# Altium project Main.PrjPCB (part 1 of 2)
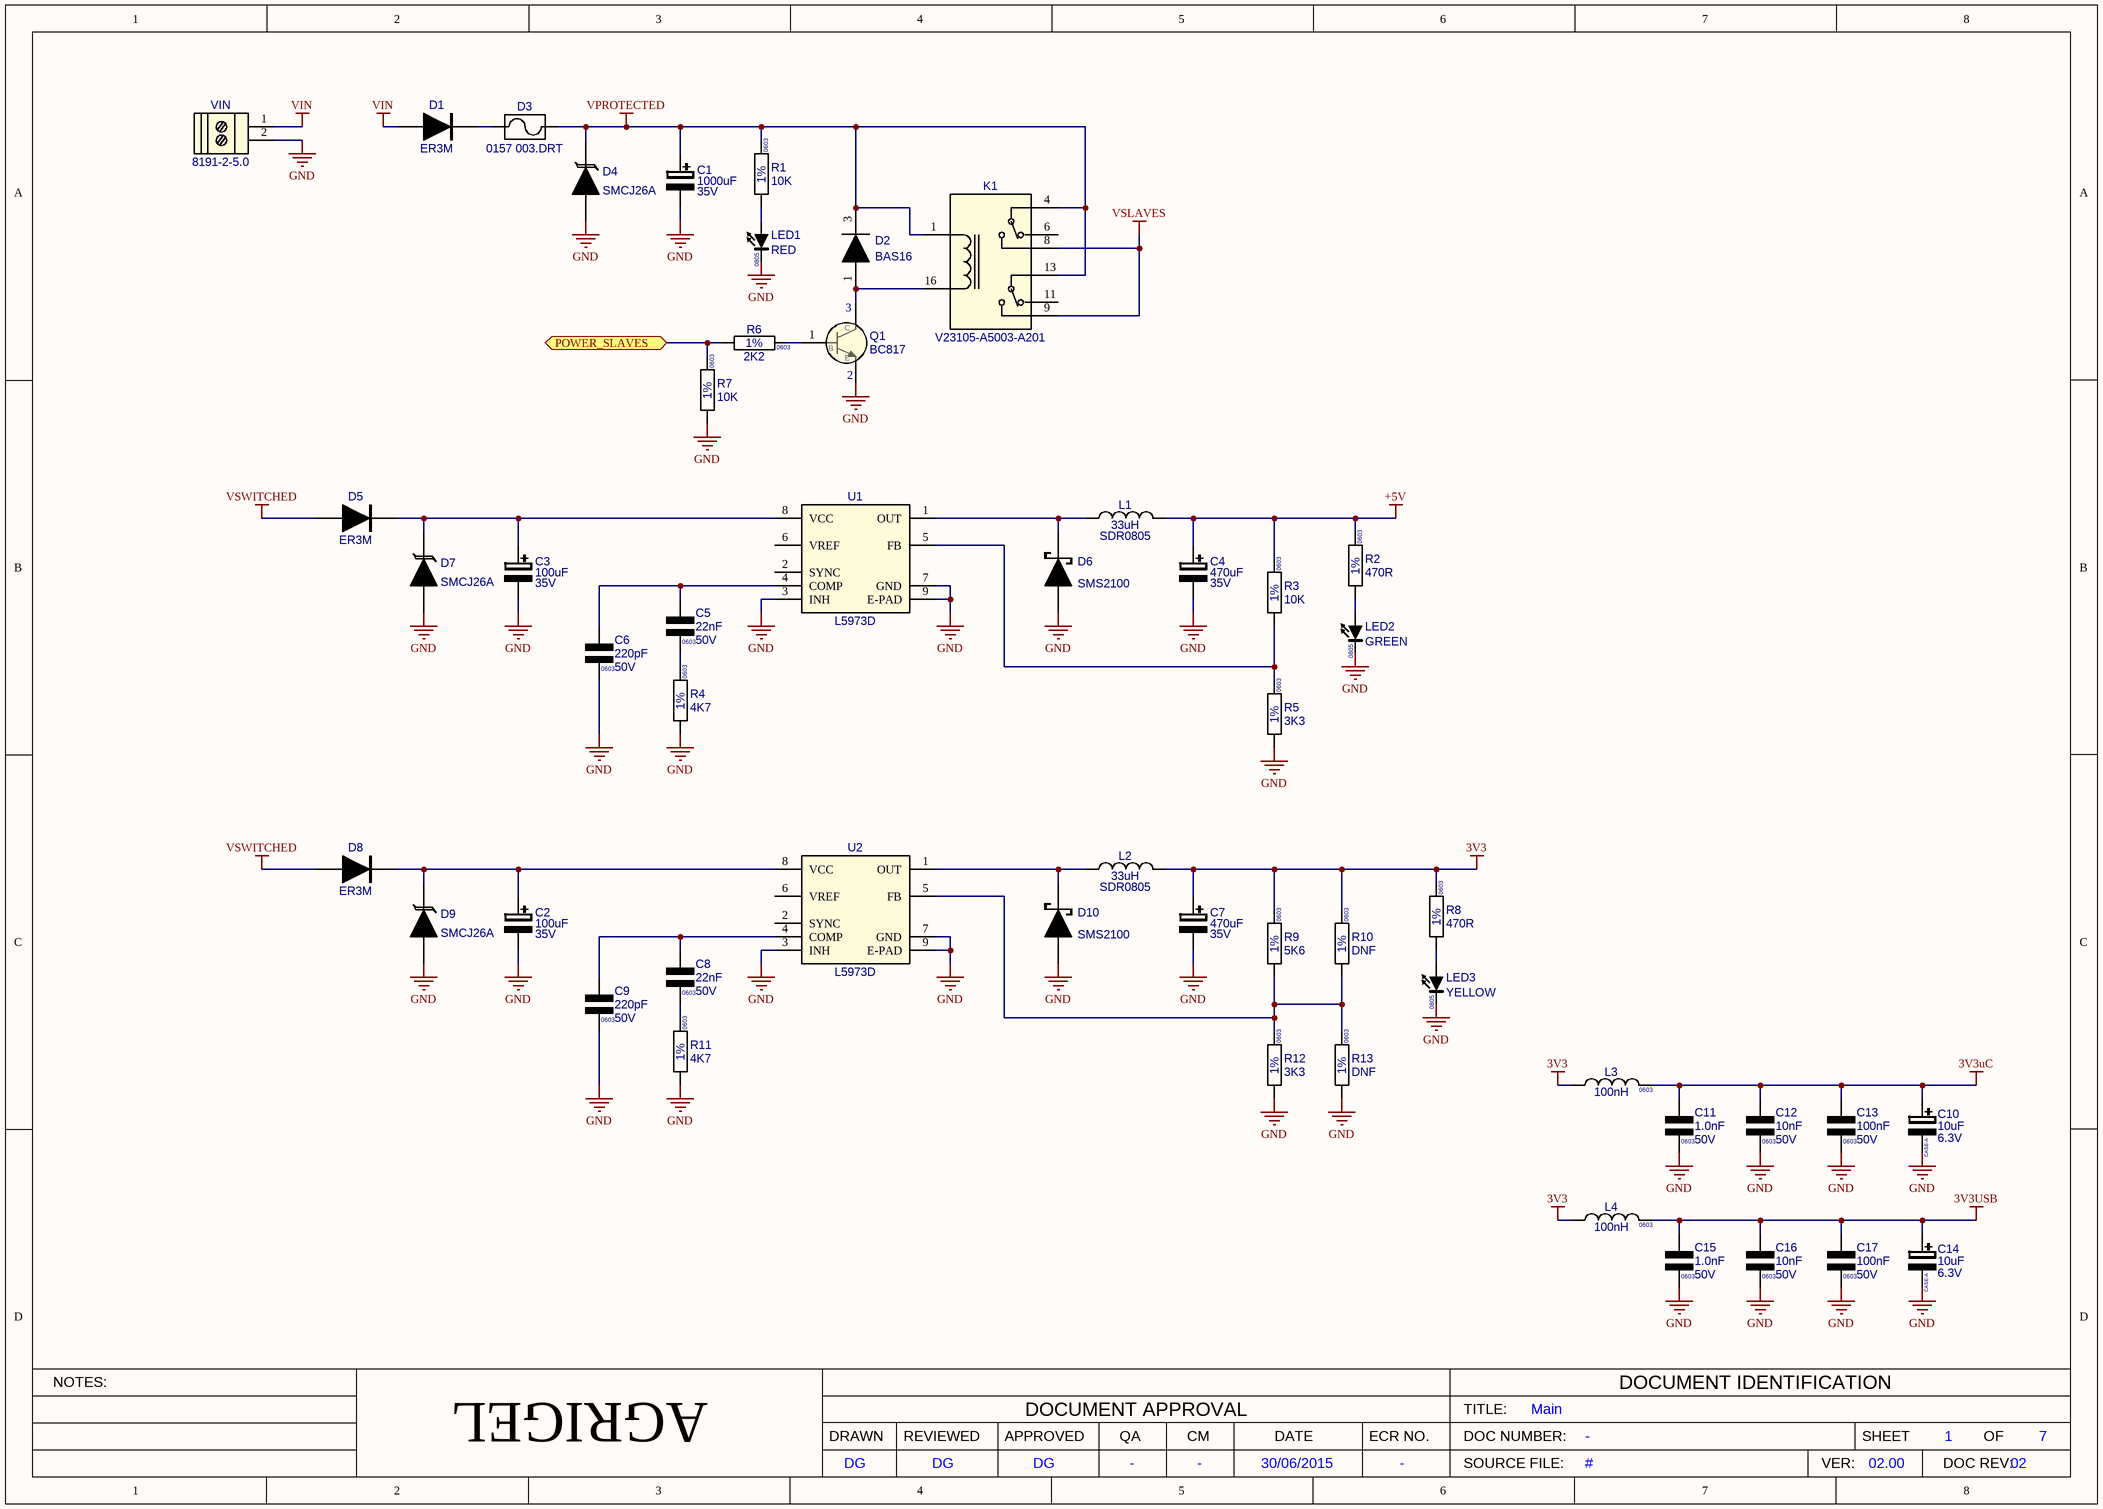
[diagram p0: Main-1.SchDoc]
Version_PCB Assy Instruction: 2; Version: 02.00; Spec_Solder Mask: GREEN; Spec_Silkscreen: WHITE EPOXY; Spec_PCB Thickness: 1.60mm; Spec_Cu Thickness: 35um; SCH_Title: Main; SCH_SheetTotal: 7; SCH_Reviewed: DG; SCH_QA: -; SCH_Number: -; SCH_FILENAME: Main-1.SCH; SCH_ECR: -; SCH_DRAWN: DG; SCH_DocRev: 02; SCH_Date: 30/06/2015; SCH_CM: -; SCH_Approved: DG; PRINT_DATE: 30/09/2014; PCB_TITLE: MAIN PCB; PCB_Plot File [Assy]: MAIN [Assy]; PCB_Plot File: MAIN [Panel]; PCB_ECRNo: -; PCB_Drawn: EDM; PCB_Drawing Number: -; PCB_DocRevision: 02; PCB_Company Name: AGRIGEL
7 sheets, 321 parts. Net scope: flat (ports and power ports of the same name join across sheets).
Board files: Main.PcbDoc, Main [Assy].PcbDoc, Main [Panel].PcbDoc
Sheets:
  Main-1.SchDoc
  Main-2.SchDoc
  Main-3.SchDoc
  Main-4.SchDoc
  Main-5.SchDoc
  Main-6.SchDoc
  Main-7.SchDoc

## Sheet Main-1.SchDoc: #
size A3; ApprovedBy: #; DrawnBy: #; DocumentNumber: 1; Revision: #; SheetNumber: 1; DocumentRevision: #; Reviewed: #; QA: #; CM: #; ECR: #; PageSetup: Record=PageOptions¦CenterHorizontal=True¦CenterVertical=True¦PrintScale=0.97¦XCorrection=1.00¦YCorrection=1.00¦PrintKind=1¦BorderSize=5000000¦LeftOffset=0¦BottomOffset=0¦Orientation=2¦PaperLength=1000¦PaperWidth=1000¦Scale=100¦PaperSource=7¦PrintQuality=-4¦MediaType=1¦DitherType=10¦PaperKind=A3¦PrintScaleMode=1

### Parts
C1  value 1000uF  Voltage: 35V  [EL-RAD-12.5x20]  (hidden comment: CAP-EL_1000uF_35V_20%-YXF)
C2  value 100uF  Voltage: 35V  [CAP-EL-SMD-10x10.5]  (hidden comment: 100uF35V-20%-EEVFC)
C3  value 100uF  Voltage: 35V  [CAP-EL-SMD-10x10.5]  (hidden comment: 100uF35V-20%-EEVFC)
C4  value 470uF  Voltage: 35V  [CAP-EL-SMD-10x10.5]  (hidden comment: 470uF-35V-20%-LZ)
C5  value 22nF  Voltage: 50V  Text1: 0603  [CAPC0603X85N]  (hidden comment: 22nF_C0603_50V_10%_X7R)
C6  value 220pF  Voltage: 50V  Text1: 0603  [CAPC0603X85N]  (hidden comment: 220pF_C0603_50V_10%_NP0)
C7  value 470uF  Voltage: 35V  [CAP-EL-SMD-10x10.5]  (hidden comment: 470uF-35V-20%-LZ)
C8  value 22nF  Voltage: 50V  Text1: 0603  [CAPC0603X85N]  (hidden comment: 22nF_C0603_50V_10%_X7R)
C9  value 220pF  Voltage: 50V  Text1: 0603  [CAPC0603X85N]  (hidden comment: 220pF_C0603_50V_10%_NP0)
C10  value 10uF  Voltage: 6.3V  Text1: CASE-A  [T491-A]  (hidden comment: 10uF_6.3V_T491A_20%)
C11  value 1.0nF  Voltage: 50V  Text1: 0603  [CAPC0603X85N]  (hidden comment: 1.0nF_C0603_50V_10%_X7R)
C12  value 10nF  Voltage: 50V  Text1: 0603  [CAPC0603X85N]  (hidden comment: 10nF_C0603_50V_10%_X7R)
C13  value 100nF  Voltage: 50V  Text1: 0603  [CAPC0603X85N]  (hidden comment: 100nF_C0603_50V_5%_X7R)
C14  value 10uF  Voltage: 6.3V  Text1: CASE-A  [T491-A]  (hidden comment: 10uF_6.3V_T491A_20%)
C15  value 1.0nF  Voltage: 50V  Text1: 0603  [CAPC0603X85N]  (hidden comment: 1.0nF_C0603_50V_10%_X7R)
C16  value 10nF  Voltage: 50V  Text1: 0603  [CAPC0603X85N]  (hidden comment: 10nF_C0603_50V_10%_X7R)
C17  value 100nF  Voltage: 50V  Text1: 0603  [CAPC0603X85N]  (hidden comment: 100nF_C0603_50V_5%_X7R)
D1  ER3M  [SMC]
D2  BAS16  [SOT23]
D3  Text1: 0157 003.DRT  [LF-0157]  (hidden comment: 0157003.DRT)
D4  SMCJ26A  [SMC]
D5  ER3M  [SMC]
D6  SMS2100  [DO-213AB]
D7  SMCJ26A  [SMC]
D8  ER3M  [SMC]
D9  SMCJ26A  [SMC]
D10  SMS2100  [DO-213AB]
K1  Part Number: V23105-A5003-A201  [REL-D2n]  (hidden comment: V23105-A5003-A201-12V)
L1  value 33uH  [SDR0805]  (hidden comment: SDR0805-330K)
L2  value 33uH  [SDR0805]  (hidden comment: SDR0805-330K)
L3  value 100nH  Text1: 0603  [L0603]  (hidden comment: 100nH-CI160808)
L4  value 100nH  Text1: 0603  [L0603]  (hidden comment: 100nH-CI160808)
LED1  value RED  Text2: 0805  [LED0805-Red]  (hidden comment: RED_0805_SMD)
LED2  value GREEN  Text2: 0805  [LED0805-Green]  (hidden comment: GREEN_0805_SMD)
LED3  value YELLOW  Text2: 0805  [LED0805-Yellow]  (hidden comment: YELLOW_0805_SMD)
Q1  BC817  [SOT23]
R1  value 10K  Tol: 1%  Text1: 0603  [RESC0603X60N]  (hidden comment: 10K_R0603_1%)
R2  value 470R  Tol: 1%  Text1: 0603  [RESC0603X60N]  (hidden comment: 470R_R0603_1%)
R3  value 10K  Tol: 1%  Text1: 0603  [RESC0603X60N]  (hidden comment: 10K_R0603_1%)
R4  value 4K7  Tol: 1%  Text1: 0603  [RESC0603X60N]  (hidden comment: 4K7_R0603_1%)
R5  value 3K3  Tol: 1%  Text1: 0603  [RESC0603X60N]  (hidden comment: 3K3_R0603_1%)
R6  value 2K2  Tol: 1%  Text1: 0603  [RESC0603X60N]  (hidden comment: 2K2_R0603_1%)
R7  value 10K  Tol: 1%  Text1: 0603  [RESC0603X60N]  (hidden comment: 10K_R0603_1%)
R8  value 470R  Tol: 1%  Text1: 0603  [RESC0603X60N]  (hidden comment: 470R_R0603_1%)
R9  value 5K6  Tol: 1%  Text1: 0603  [RESC0603X60N]  (hidden comment: 5K6_R0603_1%)
R10  value DNF  Tol: 1%  Text1: 0603  [RESC0603X60N]  (hidden comment: DNF_R0603_1%)
R11  value 4K7  Tol: 1%  Text1: 0603  [RESC0603X60N]  (hidden comment: 4K7_R0603_1%)
R12  value 3K3  Tol: 1%  Text1: 0603  [RESC0603X60N]  (hidden comment: 3K3_R0603_1%)
R13  value DNF  Tol: 1%  Text1: 0603  [RESC0603X60N]  (hidden comment: DNF_R0603_1%)
U1  Part Number: L5973D  [HSOP8]  (hidden comment: L5973D-HSOP8)
U2  Part Number: L5973D  [HSOP8]  (hidden comment: L5973D-HSOP8)
VIN  8191-2-5.0  [SCREW-TB-2-5.0]

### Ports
POWER_SLAVES

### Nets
3V3: C7.1 L2.2 L3.1 L4.1 R8.1 R9.1 R10.1
3V3uC: C10.1 C11.1 C12.1 C13.1 L3.2
3V3USB: C14.1 C15.1 C16.1 C17.1 L4.2
+5V: C4.1 L1.2 R2.1 R3.1
GND: C1.2 C2.2 C3.2 C4.2 C6.2 C7.2 C9.2 C10.2 C11.2 C12.2 C13.2 C14.2 C15.2 C16.2 C17.2 D4.2(A) D6.2(A) D7.2(A) D9.2(A) D10.2(A) LED1.1(K) LED2.1(K) LED3.1(K) Q1.2(E) R4.2 R5.2 R7.2 R11.2 R12.2 R13.2 U1.3(INH) U1.7(GND) U1.9(E-PAD) U2.3(INH) U2.7(GND) U2.9(E-PAD) VIN.2
VIN: D1.2(A) VIN.1
VPROTECTED: C1.1 D2.3(C) D3.2 D4.1(C) K1.1 K1.4 K1.13 R1.1
VSLAVES: K1.8 K1.9
VSWITCHED: D5.2(A) D8.2(A)
NetC2_1: C2.1 D8.1(C) D9.1(C) U2.8(VCC)
NetC3_1: C3.1 D5.1(C) D7.1(C) U1.8(VCC)
NetC5_1: C5.1 C6.1 U1.4(COMP)
NetC5_2: C5.2 R4.1
NetC8_1: C8.1 C9.1 U2.4(COMP)
NetC8_2: C8.2 R11.1
NetD1_1: D1.1(C) D3.1
NetD2_1: D2.1(A) K1.16 Q1.3(C)
NetD6_1: D6.1(C) L1.1 U1.1(OUT)
NetD10_1: D10.1(C) L2.1 U2.1(OUT)
NetLED1_2: LED1.2(A) R1.2
NetLED2_2: LED2.2(A) R2.2
NetLED3_2: LED3.2(A) R8.2
NetQ1_1: Q1.1(B) R6.2
NetR3_2: R3.2 R5.1 U1.5(FB)
NetR6_1: R6.1 R7.1 ; port POWER_SLAVES
NetR9_2: R9.2 R10.2 R12.1 R13.1 U2.5(FB)

Not connected (* = marked no-connect by the designer): K1 6 11; U1 2(SYNC) 6(VREF); U2 2(SYNC) 6(VREF)

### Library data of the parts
C1 = 1000uF_35V_20%_V-YXF: Cap Electrolytic THP Radial - Low Imp; Manufacturer: Rubycon; Part Number: 35YXF1000M; Tol: 20%; Reutech PN: 5910-EL-0063
C2 C3 = 100uF-35V-20%-EEVFC_V: Cap Electrolytic SMD Low Imp; Manufacturer: Panasonic; Part Number: EEVFC1V101P; Tol: 20%
C4 C7 = 470uF-35V-20%-LZ_V: Cap Electrolytic SMD Low Imp; Manufacturer: KJ Electronics; Part Number: 35LZ471MLC10×10.5EC; Tol: 20%
C5 C8 = 22nF_0603N_50V_10%_X7R_V: Cap Ceramic X7R; Manufacturer: Various; Part Number: 22nF 0603 50V 10% X7R; Board Tech: SMD; Tol: 10%
C6 C9 = 220pF_0603N_50V_10%_NP0_V: Cap Ceramic NP0; Manufacturer: Various; Part Number: 220pF 0603 50V 10% NP0; Board Tech: SMD; Tol: 10%
C10 C14 = 10uF_6.3V_CASE-A_20%_V: Cap Tantalum Case-A; Manufacturer: Various; Board Tech: SMD; Tol: 20%
C11 C15 = 1nF_0603N_50V_10%_X7R_V: Cap Ceramic X7R; Manufacturer: Various; Part Number: 1.0nF 0603 50V 10% X7R; Board Tech: SMD; Tol: 10%; Reutech PN: 5910-CA-0401
C12 C16 = 10nF_0603N_50V_10%_X7R_V: Cap Ceramic X7R; Manufacturer: Various; Part Number: 10nF 0603 50V 10% X7R; Board Tech: SMD; Tol: 10%; Reutech PN: 5910-CA-0402
C13 C17 = 100nF_0603N_50V_5%_X7R_V: Cap Ceramic X7R; Manufacturer: Various; Part Number: 100nF 0603 50V 5% X7R; Board Tech: SMD; Tol: 5%; Reutech PN: 5910-CA-0433
D1 D5 D8 = ER3M_SMC_H: Diode Rectifier (1000V 3A); Manufacturer: Diotec; Board Tech: SMD
D2 = BAS16_SOT23-3N_V: Diode Small Signal; Manufacturer: Fairchild; Board Tech: SMD
D3 = FUSE_0157003.DRT_3.0AMP: Fuse Clip and Nano Fuse; Manufacturer: Littelfuse; Board Tech: SMD; Value: 3.0A
D4 D7 D9 = SMCJ26A_V: TVS 1500W SMC; Manufacturer: Various; Board Tech: SMD
D6 D10 = SMS2100_V: Diode Schottky Rectifier 2Amp 100V; Manufacturer: Diotec; Board Tech: SMD; EDM-PN: DIO15
K1 = V23105-A5003-A201-12V: Relay DPDT 12V 3A; Manufacturer: Tyco/Axicom; Board Tech: THP
L1 L2 = 33uH_SDR0805_H: Inductor Power; Manufacturer: Bourns; Board Tech: SMD; Tol: 10%
L3 L4 = 100nH_CI160808_H: Inductor Chip SMD; Manufacturer: Bourns; Part Number: CI160808-R10J; Tol: 5%
LED1 = RED_0805_SMD_V: LED SMD 0805 Red; Manufacturer: Various; EDM-PN: LED7
LED2 = GREEN_0805_SMD_V: LED SMD 0805 Green; Manufacturer: Various; EDM-PN: LED17
LED3 = YELLOW_0805_SMD_V: LED SMD 0805 Yellow; Manufacturer: Various
Q1 = BC817_SOT23: Transistor NPN General Purpose; Manufacturer: Various; Board Tech: SMD; EDM-PN: TRN12
R1 R3 R7 = 10K_0603_V: Resistor Chip SMD; Manufacturer: Various; Part Number: 10K 0603 1%; Watt: 100mW; EDM-PN: RES120
R2 R8 = 470R_0603_V: Resistor Chip SMD; Manufacturer: Various; Part Number: 470R 0603 1%; Watt: 100mW; EDM-PN: RES127
R4 R11 = 4K7_0603_V: Resistor Chip SMD; Manufacturer: Various; Part Number: 4K7 0603 1%; Watt: 100mW
R5 R12 = 3K3_0603_V: Resistor Chip SMD; Manufacturer: Various; Part Number: 3K3 0603 1%; Watt: 100mW
R6 = 2K2_0603_H: Resistor Chip SMD; Manufacturer: Various; Part Number: 2K2 0603 1%; Watt: 100mW; EDM-PN: RES232
R9 = 5K6_0603_V: Resistor Chip SMD; Manufacturer: Various; Part Number: 5K6 0603 1%; Watt: 100mW
R10 R13 = DNF_0603_V: Resistor Chip SMD - Do not Fit; Manufacturer: Various; Watt: 100mW
U1 U2 = L5973D-HSOP8: IC Switching Regulator 2.5A; Manufacturer: ST; Board Tech: SMT
VIN = 8191-2-5.0: Screw Terminal 5.0mm Pitch; Manufacturer: Wieland; Board Tech: THP; Value: 25.161.0253.0

## Sheet Main-2.SchDoc: #
size A3; ApprovedBy: #; DrawnBy: #; DocumentNumber: 2; Revision: #; SheetNumber: 2; DocumentRevision: #; Reviewed: #; QA: #; CM: #; ECR: #; PageSetup: Record=PageOptions¦CenterHorizontal=True¦CenterVertical=True¦PrintScale=0.97¦XCorrection=1.00¦YCorrection=1.00¦PrintKind=1¦BorderSize=5000000¦LeftOffset=0¦BottomOffset=0¦Orientation=2¦PaperLength=1000¦PaperWidth=1000¦Scale=100¦PaperSource=7¦PrintQuality=-4¦MediaType=1¦DitherType=10¦PaperKind=A3¦PrintScaleMode=1
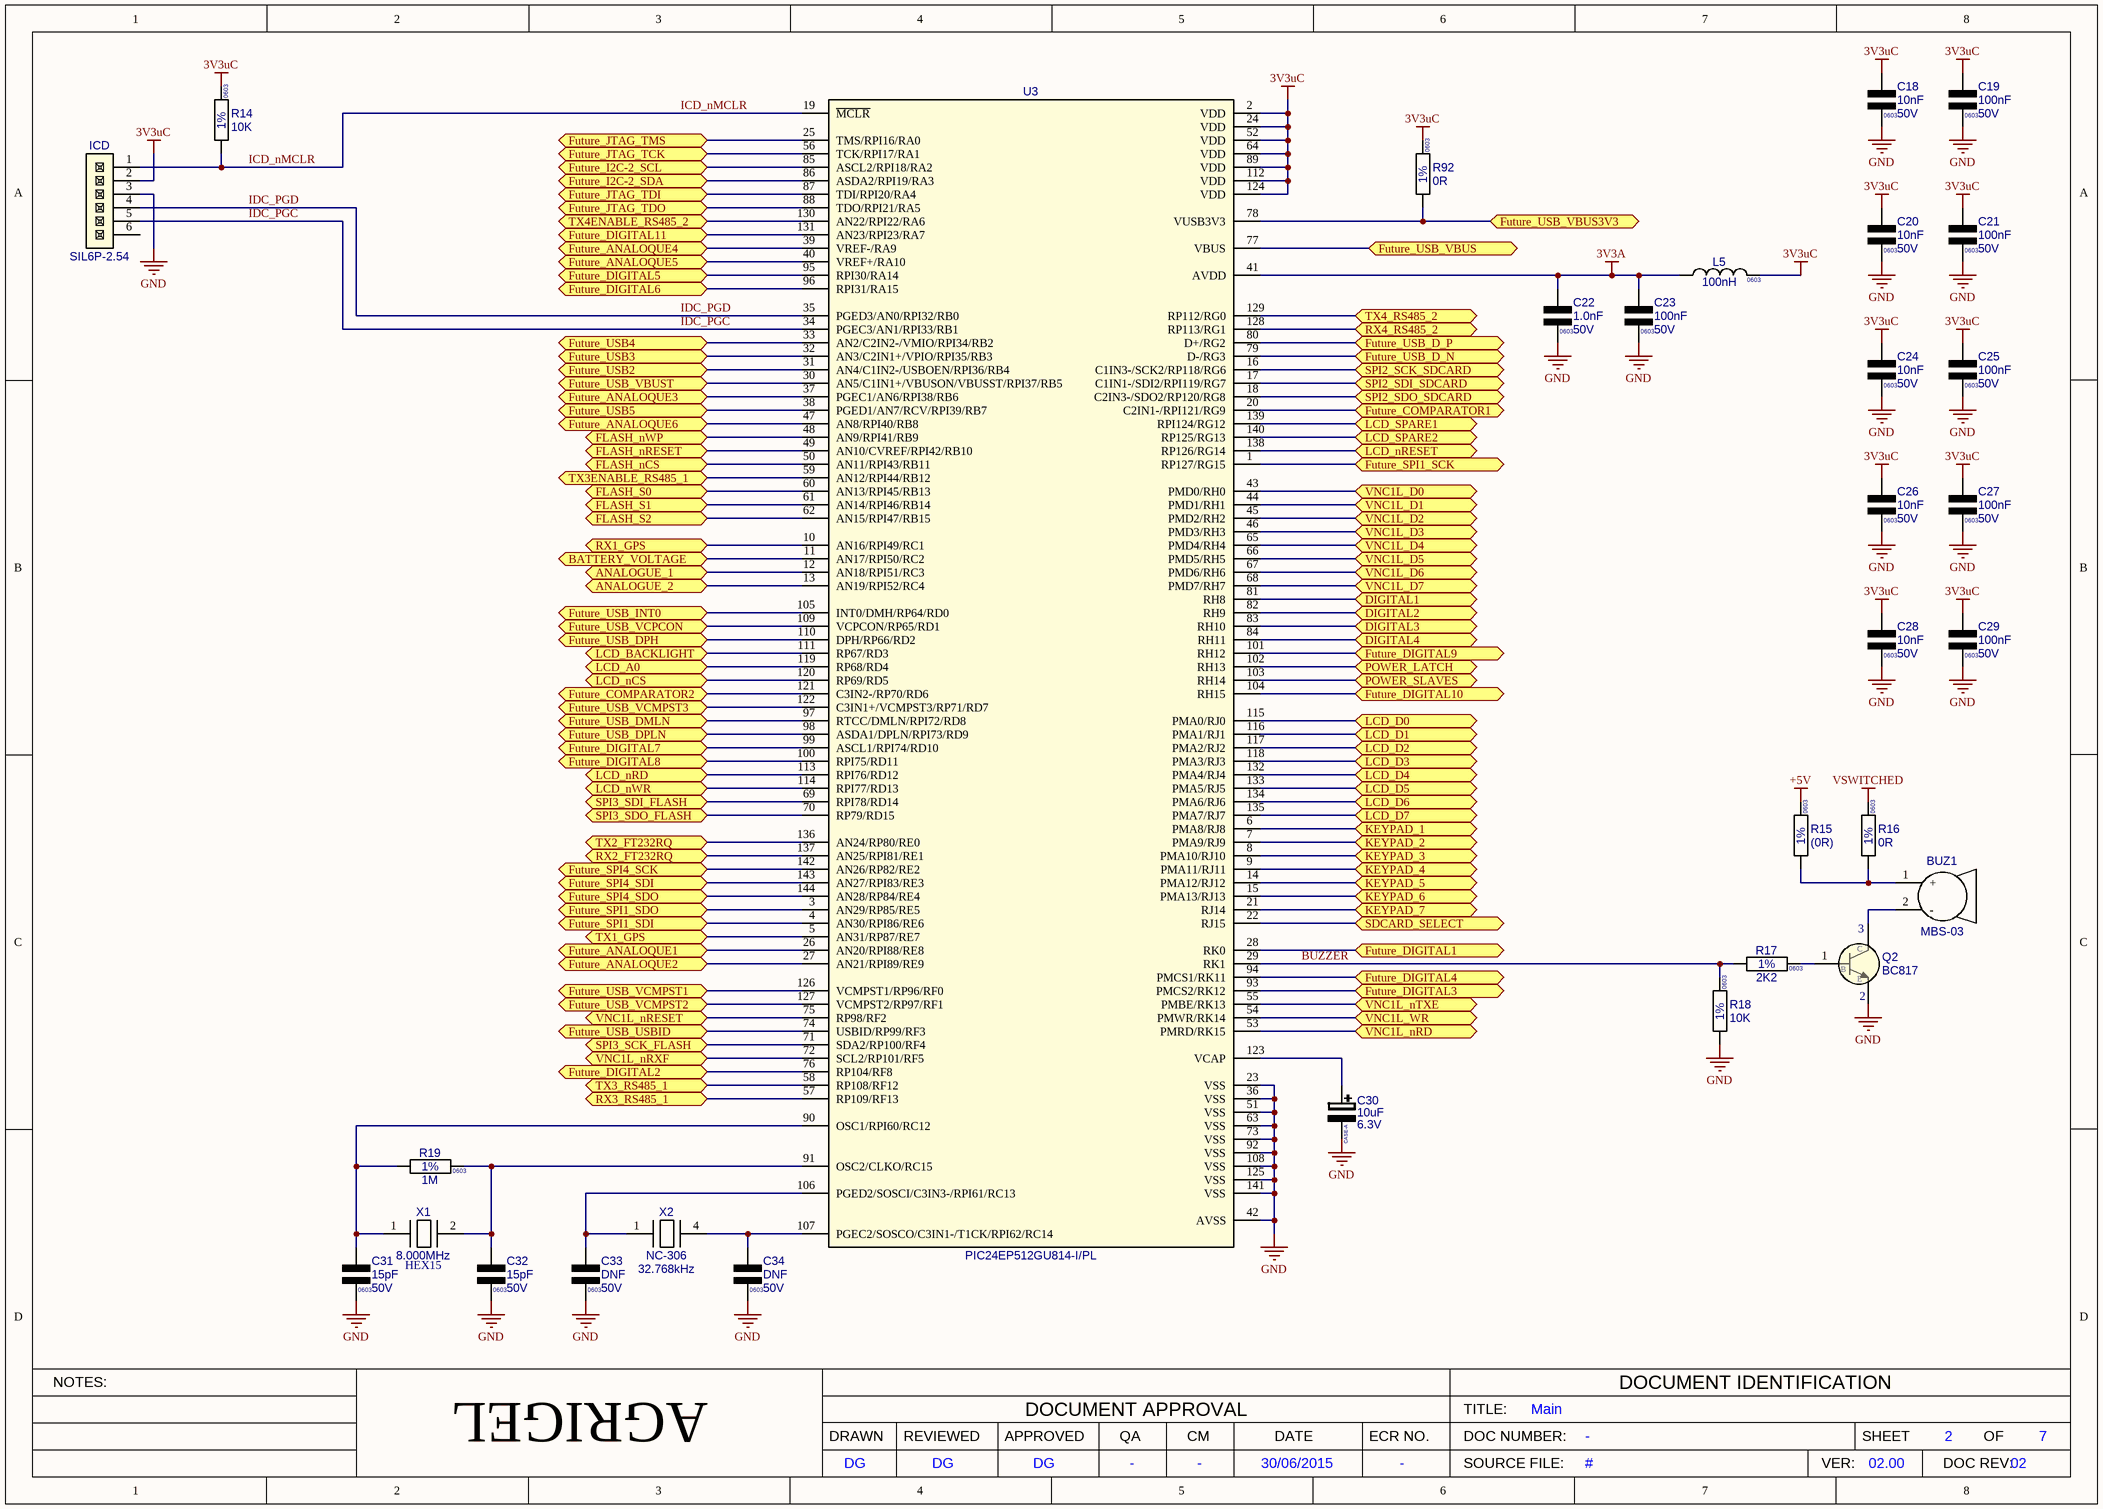
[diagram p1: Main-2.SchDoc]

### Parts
BUZ1  MBS-03  [Buzzer-MBS01-12]
C18  value 10nF  Voltage: 50V  Text1: 0603  [CAPC0603X85N]  (hidden comment: 10nF_C0603_50V_10%_X7R)
C19  value 100nF  Voltage: 50V  Text1: 0603  [CAPC0603X85N]  (hidden comment: 100nF_C0603_50V_5%_X7R)
C20  value 10nF  Voltage: 50V  Text1: 0603  [CAPC0603X85N]  (hidden comment: 10nF_C0603_50V_10%_X7R)
C21  value 100nF  Voltage: 50V  Text1: 0603  [CAPC0603X85N]  (hidden comment: 100nF_C0603_50V_5%_X7R)
C22  value 1.0nF  Voltage: 50V  Text1: 0603  [CAPC0603X85N]  (hidden comment: 1.0nF_C0603_50V_10%_X7R)
C23  value 100nF  Voltage: 50V  Text1: 0603  [CAPC0603X85N]  (hidden comment: 100nF_C0603_50V_5%_X7R)
C24  value 10nF  Voltage: 50V  Text1: 0603  [CAPC0603X85N]  (hidden comment: 10nF_C0603_50V_10%_X7R)
C25  value 100nF  Voltage: 50V  Text1: 0603  [CAPC0603X85N]  (hidden comment: 100nF_C0603_50V_5%_X7R)
C26  value 10nF  Voltage: 50V  Text1: 0603  [CAPC0603X85N]  (hidden comment: 10nF_C0603_50V_10%_X7R)
C27  value 100nF  Voltage: 50V  Text1: 0603  [CAPC0603X85N]  (hidden comment: 100nF_C0603_50V_5%_X7R)
C28  value 10nF  Voltage: 50V  Text1: 0603  [CAPC0603X85N]  (hidden comment: 10nF_C0603_50V_10%_X7R)
C29  value 100nF  Voltage: 50V  Text1: 0603  [CAPC0603X85N]  (hidden comment: 100nF_C0603_50V_5%_X7R)
C30  value 10uF  Voltage: 6.3V  Text1: CASE-A  [T491-A]  (hidden comment: 10uF_6.3V_T491A_20%)
C31  value 15pF  Voltage: 50V  Text1: 0603  [CAPC0603X85N]  (hidden comment: 15pF_C0603_50V_5%_NP0)
C32  value 15pF  Voltage: 50V  Text1: 0603  [CAPC0603X85N]  (hidden comment: 15pF_C0603_50V_5%_NP0)
C33  value DNF  Voltage: 50V  Text1: 0603  [CAPC0603X85N]  (hidden comment: DNF_C0603_50V_10%_X7R)
C34  value DNF  Voltage: 50V  Text1: 0603  [CAPC0603X85N]  (hidden comment: DNF_C0603_50V_10%_X7R)
ICD  SIL6P-2.54  [SIL6P-2.54]
L5  value 100nH  Text1: 0603  [L0603]  (hidden comment: 100nH-CI160808)
Q2  BC817  [SOT23]
R14  value 10K  Tol: 1%  Text1: 0603  [RESC0603X60N]  (hidden comment: 10K_R0603_1%)
R15  value (0R)  Tol: 1%  Text1: 0603  [RESC0603X60N]  (hidden comment: 0R_R0603_1%)
R16  value 0R  Tol: 1%  Text1: 0603  [RESC0603X60N]  (hidden comment: 0R_R0603_1%)
R17  value 2K2  Tol: 1%  Text1: 0603  [RESC0603X60N]  (hidden comment: 2K2_R0603_1%)
R18  value 10K  Tol: 1%  Text1: 0603  [RESC0603X60N]  (hidden comment: 10K_R0603_1%)
R19  value 1M  Tol: 1%  Text1: 0603  [RESC0603X60N]  (hidden comment: 1M_R0603_1%)
R92  value 0R  Tol: 1%  Text1: 0603  [RESC0603X60N]  (hidden comment: 0R_R0603_1%)
U3  PIC24EP512GU814-I/PL  [LQFP144-20x20]
X1  Text2: HEX15  Text1: 8.000MHz  [XT-HEX15]  (hidden comment: XTAL_8.000MHz_HEX15)
X2  Text1: NC-306  Part Number: 32.768kHz  [Xtal-SMD8.0x3.2 4Pin]  (hidden comment: 32.768kHz-NC-306)

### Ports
ANALOGUE_1, ANALOGUE_2, BATTERY_VOLTAGE, DIGITAL1, DIGITAL2, DIGITAL3, DIGITAL4, FLASH_nCS, FLASH_nRESET, FLASH_nWP, FLASH_S0, FLASH_S1, FLASH_S2, Future_ANALOQUE1, Future_ANALOQUE2, Future_ANALOQUE3, Future_ANALOQUE4, Future_ANALOQUE5, Future_ANALOQUE6, Future_COMPARATOR1, Future_COMPARATOR2, Future_DIGITAL1, Future_DIGITAL2, Future_DIGITAL3, Future_DIGITAL4, Future_DIGITAL5, Future_DIGITAL6, Future_DIGITAL7, Future_DIGITAL8, Future_DIGITAL9, Future_DIGITAL10, Future_DIGITAL11, Future_I2C-2_SCL, Future_I2C-2_SDA, Future_JTAG_TCK, Future_JTAG_TDI, Future_JTAG_TDO, Future_JTAG_TMS, Future_SPI1_SCK, Future_SPI1_SDI, Future_SPI1_SDO, Future_SPI4_SCK, Future_SPI4_SDI, Future_SPI4_SDO, Future_USB2, Future_USB3, Future_USB4, Future_USB5, Future_USB_D_N, Future_USB_D_P, Future_USB_DMLN, Future_USB_DPH, Future_USB_DPLN, Future_USB_INT0, Future_USB_USBID, Future_USB_VBUS, Future_USB_VBUS3V3, Future_USB_VBUST, Future_USB_VCMPST1, Future_USB_VCMPST2, Future_USB_VCMPST3, Future_USB_VCPCON, KEYPAD_1, KEYPAD_2, KEYPAD_3, KEYPAD_4, KEYPAD_5, KEYPAD_6, KEYPAD_7, LCD_A0, LCD_BACKLIGHT, LCD_D0, LCD_D1, LCD_D2, LCD_D3, LCD_D4, LCD_D5, LCD_D6, LCD_D7, LCD_nCS, LCD_nRD, LCD_nRESET, LCD_nWR, LCD_SPARE1, LCD_SPARE2, POWER_LATCH, POWER_SLAVES, RX1_GPS, RX2_FT232RQ, RX3_RS485_1, RX4_RS485_2, SDCARD_SELECT, SPI2_SCK_SDCARD, SPI2_SDI_SDCARD, SPI2_SDO_SDCARD, SPI3_SCK_FLASH, SPI3_SDI_FLASH, SPI3_SDO_FLASH, TX1_GPS, TX2_FT232RQ, TX3_RS485_1, TX3ENABLE_RS485_1, TX4_RS485_2, TX4ENABLE_RS485_2, VNC1L_D0, VNC1L_D1, VNC1L_D2, VNC1L_D3, VNC1L_D4, VNC1L_D5, VNC1L_D6, VNC1L_D7, VNC1L_nRD, VNC1L_nRESET, VNC1L_nRXF, VNC1L_nTXE, VNC1L_WR

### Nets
3V3A: C22.1 C23.1 L5.1 U3.41(AVDD)
3V3uC: C18.1 C19.1 C20.1 C21.1 C24.1 C25.1 C26.1 C27.1 C28.1 C29.1 ICD.2 L5.2 R14.1 R92.1 U3.2(VDD) U3.24(VDD) U3.52(VDD) U3.64(VDD) U3.89(VDD) U3.112(VDD) U3.124(VDD)
+5V: R15.1
GND: C18.2 C19.2 C20.2 C21.2 C22.2 C23.2 C24.2 C25.2 C26.2 C27.2 C28.2 C29.2 C30.2 C31.2 C32.2 C33.2 C34.2 ICD.3 Q2.2(E) R18.2 U3.23(VSS) U3.36(VSS) U3.42(AVSS) U3.51(VSS) U3.63(VSS) U3.73(VSS) U3.92(VSS) U3.108(VSS) U3.125(VSS) U3.141(VSS)
VSWITCHED: R16.1
BUZZER: R17.1 R18.1 U3.29(RK1)
ICD_nMCLR: ICD.1 R14.2 U3.19(~{MCLR})
IDC_PGC: ICD.5 U3.34(PGEC3/AN1/RPI33/RB1)
IDC_PGD: ICD.4 U3.35(PGED3/AN0/RPI32/RB0)
NetBUZ1_1: BUZ1.1(+) R15.2 R16.2
NetBUZ1_2: BUZ1.2(-) Q2.3(C)
NetC30_1: C30.1 U3.123(VCAP)
NetC31_1: C31.1 R19.1 U3.90(OSC1/RPI60/RC12) X1.1
NetC32_1: C32.1 R19.2 U3.91(OSC2/CLKO/RC15) X1.2
NetC33_1: C33.1 U3.106(PGED2/SOSCI/C3IN3-/RPI61/RC13) X2.1
NetC34_1: C34.1 U3.107(PGEC2/SOSCO/C3IN1-/T1CK/RPI62/RC14) X2.4
NetD16_2: U3.6(PMA8/RJ8) ; port KEYPAD_1
NetD18_2: U3.7(PMA9/RJ9) ; port KEYPAD_2
NetD21_2: U3.8(PMA10/RJ10) ; port KEYPAD_3
NetD23_2: U3.9(PMA11/RJ11) ; port KEYPAD_4
NetGPS1_20: U3.10(AN16/RPI49/RC1) ; port RX1_GPS
NetGPS1_21: U3.5(AN31/RP87/RE7) ; port TX1_GPS
NetLCD1_4: U3.119(RP68/RD4) ; port LCD_A0
NetLCD1_5: U3.114(RPI77/RD13) ; port LCD_nWR
NetLCD1_6: U3.113(RPI76/RD12) ; port LCD_nRD
NetLCD1_7: U3.115(PMA0/RJ0) ; port LCD_D0
NetLCD1_8: U3.116(PMA1/RJ1) ; port LCD_D1
NetLCD1_9: U3.117(PMA2/RJ2) ; port LCD_D2
NetLCD1_10: U3.118(PMA3/RJ3) ; port LCD_D3
NetLCD1_11: U3.132(PMA4/RJ4) ; port LCD_D4
NetLCD1_12: U3.133(PMA5/RJ5) ; port LCD_D5
NetLCD1_13: U3.134(PMA6/RJ6) ; port LCD_D6
NetLCD1_14: U3.135(PMA7/RJ7) ; port LCD_D7
NetLCD1_15: U3.120(RP69/RD5) ; port LCD_nCS
NetLCD1_16: U3.138(RP126/RG14) ; port LCD_nRESET
NetLCD-SPR1_1: U3.139(RPI124/RG12) ; port LCD_SPARE1
NetLCD-SPR2_1: U3.140(RP125/RG13) ; port LCD_SPARE2
NetP3_9: U3.1(RP127/RG15) ; port Future_SPI1_SCK
NetP3_10: U3.3(AN29/RP85/RE5) ; port Future_SPI1_SDO
NetP3_11: U3.4(AN30/RPI86/RE6) ; port Future_SPI1_SDI
NetP3_14: U3.20(C2IN1-/RPI121/RG9) ; port Future_COMPARATOR1
NetP3_15: U3.25(TMS/RPI16/RA0) ; port Future_JTAG_TMS
NetP3_16: U3.26(AN20/RPI88/RE8) ; port Future_ANALOQUE1
NetP3_17: U3.27(AN21/RPI89/RE9) ; port Future_ANALOQUE2
NetP3_18: U3.28(RK0) ; port Future_DIGITAL1
NetP3_19: U3.30(AN5/C1IN1+/VBUSON/VBUSST/RPI37/RB5) ; port Future_USB_VBUST
NetP3_20: U3.31(AN4/C1IN2-/USBOEN/RPI36/RB4) ; port Future_USB2
NetP3_21: U3.32(AN3/C2IN1+/VPIO/RPI35/RB3) ; port Future_USB3
NetP3_22: U3.33(AN2/C2IN2-/VMIO/RPI34/RB2) ; port Future_USB4
NetP3_23: U3.37(PGEC1/AN6/RPI38/RB6) ; port Future_ANALOQUE3
NetP3_24: U3.38(PGED1/AN7/RCV/RPI39/RB7) ; port Future_USB5
NetP3_25: U3.39(VREF-/RA9) ; port Future_ANALOQUE4
NetP3_26: U3.40(VREF+/RA10) ; port Future_ANALOQUE5
NetP3_27: U3.47(AN8/RPI40/RB8) ; port Future_ANALOQUE6
NetP3_28: U3.56(TCK/RPI17/RA1) ; port Future_JTAG_TCK
NetP3_29: U3.74(USBID/RP99/RF3) ; port Future_USB_USBID
NetP3_30: U3.76(RP104/RF8) ; port Future_DIGITAL2
NetP3_31: U3.77(VBUS) ; port Future_USB_VBUS
NetP3_32: R92.2 U3.78(VUSB3V3) ; port Future_USB_VBUS3V3
NetP3_33: U3.79(D-/RG3) ; port Future_USB_D_N
NetP3_34: U3.80(D+/RG2) ; port Future_USB_D_P
NetP4_9: U3.85(ASCL2/RPI18/RA2) ; port Future_I2C-2_SCL
NetP4_10: U3.86(ASDA2/RPI19/RA3) ; port Future_I2C-2_SDA
NetP4_11: U3.87(TDI/RPI20/RA4) ; port Future_JTAG_TDI
NetP4_12: U3.88(TDO/RPI21/RA5) ; port Future_JTAG_TDO
NetP4_13: U3.93(PMCS2/RK12) ; port Future_DIGITAL3
NetP4_14: U3.94(PMCS1/RK11) ; port Future_DIGITAL4
NetP4_15: U3.95(RPI30/RA14) ; port Future_DIGITAL5
NetP4_16: U3.96(RPI31/RA15) ; port Future_DIGITAL6
NetP4_17: U3.97(RTCC/DMLN/RPI72/RD8) ; port Future_USB_DMLN
NetP4_18: U3.98(ASDA1/DPLN/RPI73/RD9) ; port Future_USB_DPLN
NetP4_19: U3.99(ASCL1/RPI74/RD10) ; port Future_DIGITAL7
NetP4_20: U3.100(RPI75/RD11) ; port Future_DIGITAL8
NetP4_21: U3.101(RH12) ; port Future_DIGITAL9
NetP4_22: U3.104(RH15) ; port Future_DIGITAL10
NetP4_23: U3.105(INT0/DMH/RP64/RD0) ; port Future_USB_INT0
NetP4_24: U3.109(VCPCON/RP65/RD1) ; port Future_USB_VCPCON
NetP4_25: U3.110(DPH/RP66/RD2) ; port Future_USB_DPH
NetP4_26: U3.121(C3IN2-/RP70/RD6) ; port Future_COMPARATOR2
NetP4_27: U3.122(C3IN1+/VCMPST3/RP71/RD7) ; port Future_USB_VCMPST3
NetP4_28: U3.126(VCMPST1/RP96/RF0) ; port Future_USB_VCMPST1
NetP4_29: U3.127(VCMPST2/RP97/RF1) ; port Future_USB_VCMPST2
NetP4_30: U3.131(AN23/RPI23/RA7) ; port Future_DIGITAL11
NetP4_31: U3.142(AN26/RP82/RE2) ; port Future_SPI4_SCK
NetP4_32: U3.143(AN27/RPI83/RE3) ; port Future_SPI4_SDI
NetP4_33: U3.144(AN28/RP84/RE4) ; port Future_SPI4_SDO
NetQ2_1: Q2.1(B) R17.2
NetQ4_3: U3.81(RH8) ; port DIGITAL1
NetQ6_3: U3.82(RH9) ; port DIGITAL2
NetQ9_3: U3.83(RH10) ; port DIGITAL3
NetQ12_3: U3.84(RH11) ; port DIGITAL4
NetQ17_3: U3.14(PMA12/RJ12) ; port KEYPAD_5
NetQ18_3: U3.15(PMA13/RJ13) ; port KEYPAD_6
NetQ20_3: U3.21(RJ14) ; port KEYPAD_7
NetR6_1: U3.103(RH14) ; port POWER_SLAVES
NetR23_2: U3.11(AN17/RPI50/RC2) ; port BATTERY_VOLTAGE
NetR31_2: U3.12(AN18/RPI51/RC3) ; port ANALOGUE_1
NetR39_2: U3.13(AN19/RPI52/RC4) ; port ANALOGUE_2
NetR47_2: U3.58(RP108/RF12) ; port TX3_RS485_1
NetR53_1: U3.59(AN12/RPI44/RB12) ; port TX3ENABLE_RS485_1
NetR60_2: U3.129(RP112/RG0) ; port TX4_RS485_2
NetR67_1: U3.130(AN22/RPI22/RA6) ; port TX4ENABLE_RS485_2
NetR73_1: U3.48(AN9/RPI41/RB9) ; port FLASH_nWP
NetR74_2: U3.50(AN11/RPI43/RB11) ; port FLASH_nCS
NetR93_1: U3.111(RP67/RD3) ; port LCD_BACKLIGHT
NetR103_1: U3.102(RH13) ; port POWER_LATCH
NetR106_1: U3.75(RP98/RF2) ; port VNC1L_nRESET
NetR130_2: U3.43(PMD0/RH0) ; port VNC1L_D0
NetR131_2: U3.44(PMD1/RH1) ; port VNC1L_D1
NetR132_2: U3.45(PMD2/RH2) ; port VNC1L_D2
NetR133_2: U3.46(PMD3/RH3) ; port VNC1L_D3
NetSD1_2: U3.22(RJ15) ; port SDCARD_SELECT
NetSD1_3: U3.18(C2IN3-/SDO2/RP120/RG8) ; port SPI2_SDO_SDCARD
NetSD1_5: U3.16(C1IN3-/SCK2/RP118/RG6) ; port SPI2_SCK_SDCARD
NetSD1_7: U3.17(C1IN1-/SDI2/RPI119/RG7) ; port SPI2_SDI_SDCARD
NetU3_49: U3.49(AN10/CVREF/RPI42/RB10) ; port FLASH_nRESET
NetU3_53: U3.53(PMRD/RK15) ; port VNC1L_nRD
NetU3_54: U3.54(PMWR/RK14) ; port VNC1L_WR
NetU3_55: U3.55(PMBE/RK13) ; port VNC1L_nTXE
NetU3_57: U3.57(RP109/RF13) ; port RX3_RS485_1
NetU3_60: U3.60(AN13/RPI45/RB13) ; port FLASH_S0
NetU3_61: U3.61(AN14/RPI46/RB14) ; port FLASH_S1
NetU3_62: U3.62(AN15/RPI47/RB15) ; port FLASH_S2
NetU3_65: U3.65(PMD4/RH4) ; port VNC1L_D4
NetU3_66: U3.66(PMD5/RH5) ; port VNC1L_D5
NetU3_67: U3.67(PMD6/RH6) ; port VNC1L_D6
NetU3_68: U3.68(PMD7/RH7) ; port VNC1L_D7
NetU3_69: U3.69(RPI78/RD14) ; port SPI3_SDI_FLASH
NetU3_70: U3.70(RP79/RD15) ; port SPI3_SDO_FLASH
NetU3_71: U3.71(SDA2/RP100/RF4) ; port SPI3_SCK_FLASH
NetU3_72: U3.72(SCL2/RP101/RF5) ; port VNC1L_nRXF
NetU3_128: U3.128(RP113/RG1) ; port RX4_RS485_2
NetU3_136: U3.136(AN24/RP80/RE0) ; port TX2_FT232RQ
NetU3_137: U3.137(AN25/RPI81/RE1) ; port RX2_FT232RQ

Not connected (* = marked no-connect by the designer): ICD 6

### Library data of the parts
BUZ1 = BUZZER_MBS-03_THP: Buzzer Magnetic; Manufacturer: KAYER INDUSTRIAL; Board Tech: THP
C18 C20 C24 C26 C28 = 10nF_0603N_50V_10%_X7R_V: as C12 on sheet Main-1
C19 C21 C23 C25 C27 C29 = 100nF_0603N_50V_5%_X7R_V: as C13 on sheet Main-1
C22 = 1nF_0603N_50V_10%_X7R_V: as C11 on sheet Main-1
C30 = 10uF_6.3V_CASE-A_20%_V: as C10 on sheet Main-1
C31 C32 = 15pF_0603N_50V_5%_NP0_V: Cap Ceramic NP0; Manufacturer: Various; Part Number: 15pF 0603 50V 5% NP0; Board Tech: SMD; Tol: 5%
C33 C34 = DNF_0603N_50V_10%_X7R_V: Cap Ceramic X7R - Do not Fit; Manufacturer: Various; Board Tech: SMD; Tol: 10%
ICD = SIL6P-2.54: Header SIL Male THP, 2.54mm Pitch; Manufacturer: Various
L5 = 100nH_CI160808_H: as L3 on sheet Main-1
Q2 = BC817_SOT23: as Q1 on sheet Main-1
R14 R18 = 10K_0603_V: as R1 on sheet Main-1
R15 = 0R_0603_V-DNF: Resistor Chip SMD - Do not Fit; Manufacturer: Various; Part Number: DNF - 0R 0603 1%; Watt: 100mW
R16 R92 = 0R_0603_V: Resistor Chip SMD; Manufacturer: Various; Part Number: 0R 0603 1%; Watt: 100mW; EDM-PN: RES117
R17 = 2K2_0603_H: as R6 on sheet Main-1
R19 = 1M_0603_H: Resistor Chip SMD; Manufacturer: Various; Part Number: 1M 0603 1%; Watt: 100mW
U3 = PIC24EP512GU814-I/PL_LQFP144: IC Microcontroller 16-Bit and Digital Signal Controller; Manufacturer: Microchip; Board Tech: SMD
X1 = XTAL_8.000MHz_HEX15: Crystal - HEX15; Manufacturer: Horizon; Part Number: 8.000MHz HEX15; Board Tech: SMD; Value: XTAL_8.000MHz-HEX15
X2 = XTAL_32.768kHz-NC-306: Crystal - NC-306 (12pF); Manufacturer: Arrow; Board Tech: SMD; EDM-PN: CRY41; Value: NC-306 32.768kHz

## Sheet Main-3.SchDoc: #
size A3; ApprovedBy: #; DrawnBy: #; DocumentNumber: 3; Revision: #; SheetNumber: 3; DocumentRevision: #; Reviewed: #; QA: #; CM: #; ECR: #; PageSetup: Record=PageOptions|CenterHorizontal=True|CenterVertical=True|PrintScale=0.97|XCorrection=1.00|YCorrection=1.00|PrintKind=1|BorderSize=5000000|LeftOffset=0|BottomOffset=0|Orientation=2|PaperLength=1000|PaperWidth=1000|Scale=100|PaperSource=7|PrintQuality=-4|MediaType=1|DitherType=10|PaperKind=A3|PrintScaleMode=1
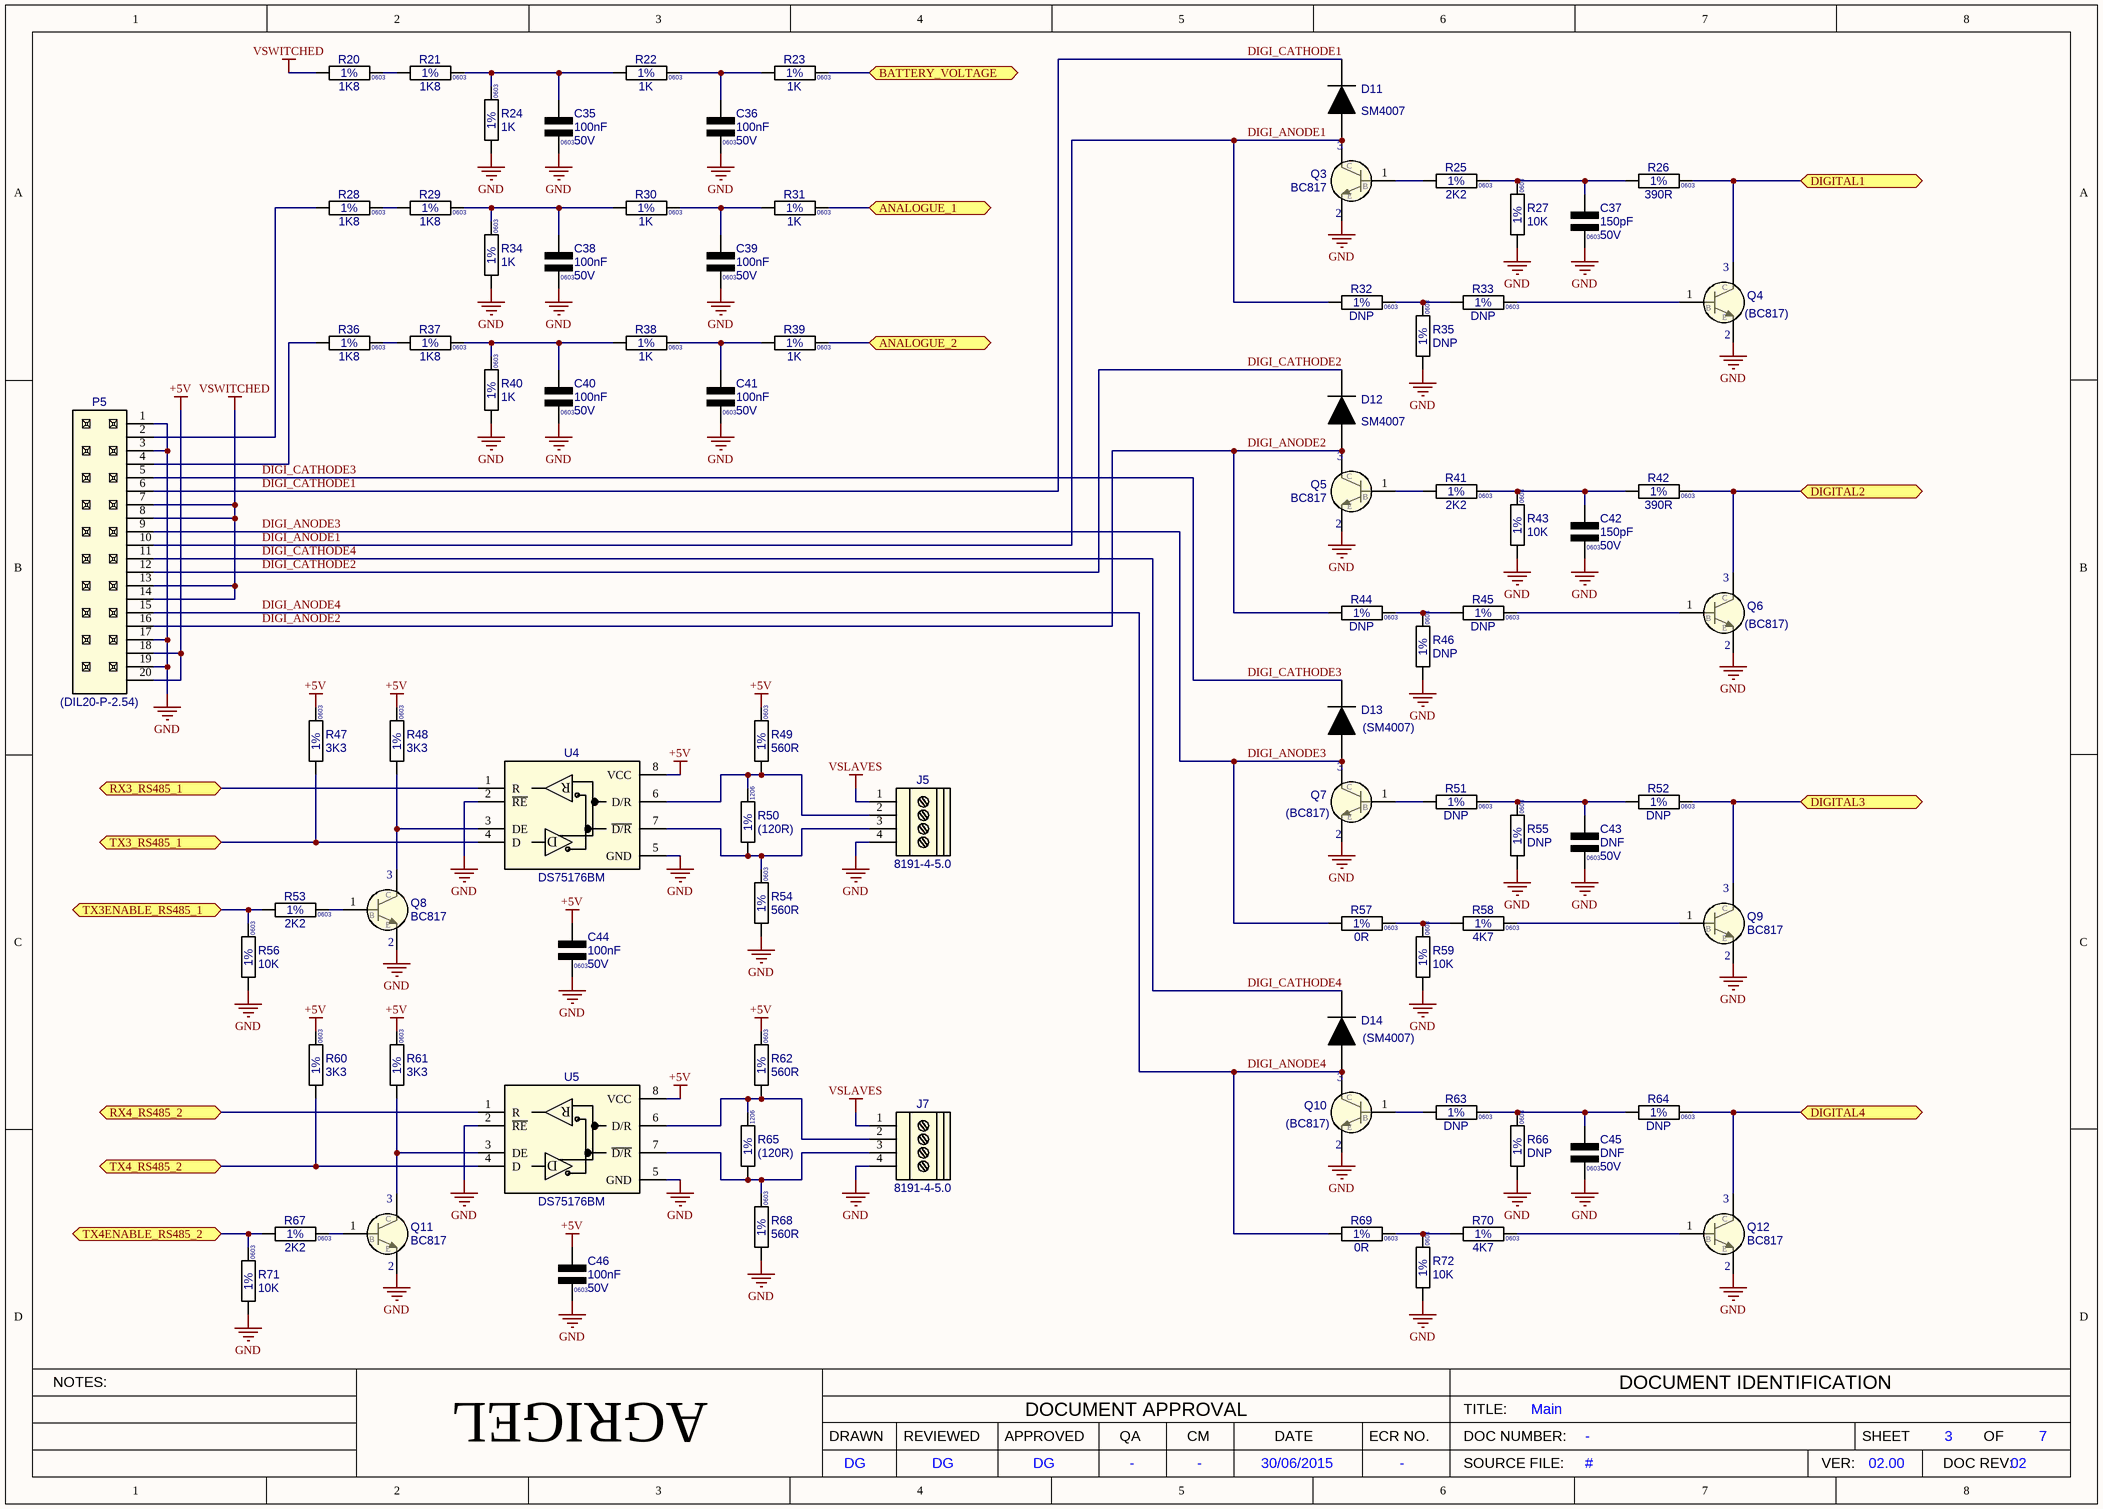
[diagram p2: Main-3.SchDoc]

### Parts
C35  value 100nF  Voltage: 50V  Text1: 0603  [CAPC0603X85N]  (hidden comment: 100nF_C0603_50V_5%_X7R)
C36  value 100nF  Voltage: 50V  Text1: 0603  [CAPC0603X85N]  (hidden comment: 100nF_C0603_50V_5%_X7R)
C37  value 150pF  Voltage: 50V  Text1: 0603  [CAPC0603X85N]  (hidden comment: 150pF_C0603_50V_5%_NP0)
C38  value 100nF  Voltage: 50V  Text1: 0603  [CAPC0603X85N]  (hidden comment: 100nF_C0603_50V_5%_X7R)
C39  value 100nF  Voltage: 50V  Text1: 0603  [CAPC0603X85N]  (hidden comment: 100nF_C0603_50V_5%_X7R)
C40  value 100nF  Voltage: 50V  Text1: 0603  [CAPC0603X85N]  (hidden comment: 100nF_C0603_50V_5%_X7R)
C41  value 100nF  Voltage: 50V  Text1: 0603  [CAPC0603X85N]  (hidden comment: 100nF_C0603_50V_5%_X7R)
C42  value 150pF  Voltage: 50V  Text1: 0603  [CAPC0603X85N]  (hidden comment: 150pF_C0603_50V_5%_NP0)
C43  value DNF  Voltage: 50V  Text1: 0603  [CAPC0603X85N]  (hidden comment: DNF_C0603_50V_10%_X7R)
C44  value 100nF  Voltage: 50V  Text1: 0603  [CAPC0603X85N]  (hidden comment: 100nF_C0603_50V_5%_X7R)
C45  value DNF  Voltage: 50V  Text1: 0603  [CAPC0603X85N]  (hidden comment: DNF_C0603_50V_10%_X7R)
C46  value 100nF  Voltage: 50V  Text1: 0603  [CAPC0603X85N]  (hidden comment: 100nF_C0603_50V_5%_X7R)
D11  SM4007  [DO-213AB]
D12  SM4007  [DO-213AB]
D13  value (SM4007)  [DO-213AB]  (hidden comment: SM4007-DNF)
D14  value (SM4007)  [DO-213AB]  (hidden comment: SM4007-DNF)
J5  8191-4-5.0  [SCREW-TB-4-5.0]
J7  8191-4-5.0  [SCREW-TB-4-5.0]
P5  value (DIL20-P-2.54)  [DIL20-P-2.54]  (hidden comment: DIL20P-2.54-DNF)
Q3  BC817  [SOT23]
Q4  value (BC817)  [SOT23]  (hidden comment: BC817-DNF)
Q5  BC817  [SOT23]
Q6  value (BC817)  [SOT23]  (hidden comment: BC817-DNF)
Q7  value (BC817)  [SOT23]  (hidden comment: BC817-DNF)
Q8  BC817  [SOT23]
Q9  BC817  [SOT23]
Q10  value (BC817)  [SOT23]  (hidden comment: BC817-DNF)
Q11  BC817  [SOT23]
Q12  BC817  [SOT23]
R20  value 1K8  Tol: 1%  Text1: 0603  [RESC0603X60N]  (hidden comment: 1K8_R0603_1%)
R21  value 1K8  Tol: 1%  Text1: 0603  [RESC0603X60N]  (hidden comment: 1K8_R0603_1%)
R22  value 1K  Tol: 1%  Text1: 0603  [RESC0603X60N]  (hidden comment: 1K_R0603_1%)
R23  value 1K  Tol: 1%  Text1: 0603  [RESC0603X60N]  (hidden comment: 1K_R0603_1%)
R24  value 1K  Tol: 1%  Text1: 0603  [RESC0603X60N]  (hidden comment: 1K_R0603_1%)
R25  value 2K2  Tol: 1%  Text1: 0603  [RESC0603X60N]  (hidden comment: 2K2_R0603_1%)
R26  value 390R  Tol: 1%  Text1: 0603  [RESC0603X60N]  (hidden comment: 390R_R0603_1%)
R27  value 10K  Tol: 1%  Text1: 0603  [RESC0603X60N]  (hidden comment: 10K_R0603_1%)
R28  value 1K8  Tol: 1%  Text1: 0603  [RESC0603X60N]  (hidden comment: 1K8_R0603_1%)
R29  value 1K8  Tol: 1%  Text1: 0603  [RESC0603X60N]  (hidden comment: 1K8_R0603_1%)
R30  value 1K  Tol: 1%  Text1: 0603  [RESC0603X60N]  (hidden comment: 1K_R0603_1%)
R31  value 1K  Tol: 1%  Text1: 0603  [RESC0603X60N]  (hidden comment: 1K_R0603_1%)
R32  value DNP  Tol: 1%  Text1: 0603  [RESC0603X60N]  (hidden comment: DNP_R0603_1%)
R33  value DNP  Tol: 1%  Text1: 0603  [RESC0603X60N]  (hidden comment: DNP_R0603_1%)
R34  value 1K  Tol: 1%  Text1: 0603  [RESC0603X60N]  (hidden comment: 1K_R0603_1%)
R35  value DNP  Tol: 1%  Text1: 0603  [RESC0603X60N]  (hidden comment: DNP_R0603_1%)
R36  value 1K8  Tol: 1%  Text1: 0603  [RESC0603X60N]  (hidden comment: 1K8_R0603_1%)
R37  value 1K8  Tol: 1%  Text1: 0603  [RESC0603X60N]  (hidden comment: 1K8_R0603_1%)
R38  value 1K  Tol: 1%  Text1: 0603  [RESC0603X60N]  (hidden comment: 1K_R0603_1%)
R39  value 1K  Tol: 1%  Text1: 0603  [RESC0603X60N]  (hidden comment: 1K_R0603_1%)
R40  value 1K  Tol: 1%  Text1: 0603  [RESC0603X60N]  (hidden comment: 1K_R0603_1%)
R41  value 2K2  Tol: 1%  Text1: 0603  [RESC0603X60N]  (hidden comment: 2K2_R0603_1%)
R42  value 390R  Tol: 1%  Text1: 0603  [RESC0603X60N]  (hidden comment: 390R_R0603_1%)
R43  value 10K  Tol: 1%  Text1: 0603  [RESC0603X60N]  (hidden comment: 10K_R0603_1%)
R44  value DNP  Tol: 1%  Text1: 0603  [RESC0603X60N]  (hidden comment: DNP_R0603_1%)
R45  value DNP  Tol: 1%  Text1: 0603  [RESC0603X60N]  (hidden comment: DNP_R0603_1%)
R46  value DNP  Tol: 1%  Text1: 0603  [RESC0603X60N]  (hidden comment: DNP_R0603_1%)
R47  value 3K3  Tol: 1%  Text1: 0603  [RESC0603X60N]  (hidden comment: 3K3_R0603_1%)
R48  value 3K3  Tol: 1%  Text1: 0603  [RESC0603X60N]  (hidden comment: 3K3_R0603_1%)
R49  value 560R  Tol: 1%  Text1: 0603  [RESC0603X60N]  (hidden comment: 560R_R0603_1%)
R50  value (120R)  Tol: 1%  Text1: 1206  [RESC1206X71N]  (hidden comment: 120R_R1206_1%-DNF)
R51  value DNP  Tol: 1%  Text1: 0603  [RESC0603X60N]  (hidden comment: DNP_R0603_1%)
R52  value DNP  Tol: 1%  Text1: 0603  [RESC0603X60N]  (hidden comment: DNP_R0603_1%)
R53  value 2K2  Tol: 1%  Text1: 0603  [RESC0603X60N]  (hidden comment: 2K2_R0603_1%)
R54  value 560R  Tol: 1%  Text1: 0603  [RESC0603X60N]  (hidden comment: 560R_R0603_1%)
R55  value DNP  Tol: 1%  Text1: 0603  [RESC0603X60N]  (hidden comment: DNP_R0603_1%)
R56  value 10K  Tol: 1%  Text1: 0603  [RESC0603X60N]  (hidden comment: 10K_R0603_1%)
R57  value 0R  Tol: 1%  Text1: 0603  [RESC0603X60N]  (hidden comment: 0R_R0603_1%)
R58  value 4K7  Tol: 1%  Text1: 0603  [RESC0603X60N]  (hidden comment: 4K7_R0603_1%)
R59  value 10K  Tol: 1%  Text1: 0603  [RESC0603X60N]  (hidden comment: 10K_R0603_1%)
R60  value 3K3  Tol: 1%  Text1: 0603  [RESC0603X60N]  (hidden comment: 3K3_R0603_1%)
R61  value 3K3  Tol: 1%  Text1: 0603  [RESC0603X60N]  (hidden comment: 3K3_R0603_1%)
R62  value 560R  Tol: 1%  Text1: 0603  [RESC0603X60N]  (hidden comment: 560R_R0603_1%)
R63  value DNP  Tol: 1%  Text1: 0603  [RESC0603X60N]  (hidden comment: DNP_R0603_1%)
R64  value DNP  Tol: 1%  Text1: 0603  [RESC0603X60N]  (hidden comment: DNP_R0603_1%)
R65  value (120R)  Tol: 1%  Text1: 1206  [RESC1206X71N]  (hidden comment: 120R_R1206_1%-DNF)
R66  value DNP  Tol: 1%  Text1: 0603  [RESC0603X60N]  (hidden comment: DNP_R0603_1%)
R67  value 2K2  Tol: 1%  Text1: 0603  [RESC0603X60N]  (hidden comment: 2K2_R0603_1%)
R68  value 560R  Tol: 1%  Text1: 0603  [RESC0603X60N]  (hidden comment: 560R_R0603_1%)
R69  value 0R  Tol: 1%  Text1: 0603  [RESC0603X60N]  (hidden comment: 0R_R0603_1%)
R70  value 4K7  Tol: 1%  Text1: 0603  [RESC0603X60N]  (hidden comment: 4K7_R0603_1%)
R71  value 10K  Tol: 1%  Text1: 0603  [RESC0603X60N]  (hidden comment: 10K_R0603_1%)
R72  value 10K  Tol: 1%  Text1: 0603  [RESC0603X60N]  (hidden comment: 10K_R0603_1%)
U4  DS75176BM  [SO8]
U5  DS75176BM  [SO8]

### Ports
ANALOGUE_1, ANALOGUE_2, BATTERY_VOLTAGE, DIGITAL1, DIGITAL2, DIGITAL3, DIGITAL4, RX3_RS485_1, RX4_RS485_2, TX3_RS485_1, TX3ENABLE_RS485_1, TX4_RS485_2, TX4ENABLE_RS485_2

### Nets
+5V: C44.1 C46.1 P5.18 P5.20 R47.1 R48.1 R49.1 R60.1 R61.1 R62.1 U4.8(VCC) U5.8(VCC)
GND: C35.2 C36.2 C37.2 C38.2 C39.2 C40.2 C41.2 C42.2 C43.2 C44.2 C45.2 C46.2 J5.4 J7.4 P5.1 P5.3 P5.17 P5.19 Q3.2(E) Q4.2(E) Q5.2(E) Q6.2(E) Q7.2(E) Q8.2(E) Q9.2(E) Q10.2(E) Q11.2(E) Q12.2(E) R24.2 R27.2 R34.2 R35.2 R40.2 R43.2 R46.2 R54.2 R55.2 R56.2 R59.2 R66.2 R68.2 R71.2 R72.2 U4.2(~{RE}) U4.5(GND) U5.2(~{RE}) U5.5(GND)
VSLAVES: J5.1 J7.1
VSWITCHED: P5.7 P5.8 P5.13 P5.14 R20.1
DIGI_ANODE1: D11.2(A) P5.10 Q3.3(C) R32.1
DIGI_ANODE2: D12.2(A) P5.16 Q5.3(C) R44.1
DIGI_ANODE3: D13.2(A) P5.9 Q7.3(C) R57.1
DIGI_ANODE4: D14.2(A) P5.15 Q10.3(C) R69.1
DIGI_CATHODE1: D11.1(C) P5.6
DIGI_CATHODE2: D12.1(C) P5.12
DIGI_CATHODE3: D13.1(C) P5.5
DIGI_CATHODE4: D14.1(C) P5.11
NetC35_1: C35.1 R21.2 R22.1 R24.1
NetC36_1: C36.1 R22.2 R23.1
NetC37_1: C37.1 R25.2 R26.1 R27.1
NetC38_1: C38.1 R29.2 R30.1 R34.1
NetC39_1: C39.1 R30.2 R31.1
NetC40_1: C40.1 R37.2 R38.1 R40.1
NetC41_1: C41.1 R38.2 R39.1
NetC42_1: C42.1 R41.2 R42.1 R43.1
NetC43_1: C43.1 R51.2 R52.1 R55.1
NetC45_1: C45.1 R63.2 R64.1 R66.1
NetJ5_2: J5.2 R49.2 R50.1 U4.6(D/R)
NetJ5_3: J5.3 R50.2 R54.1 U4.7(~{D/R})
NetJ7_2: J7.2 R62.2 R65.1 U5.6(D/R)
NetJ7_3: J7.3 R65.2 R68.1 U5.7(~{D/R})
NetP5_2: P5.2 R28.1
NetP5_4: P5.4 R36.1
NetQ3_1: Q3.1(B) R25.1
NetQ4_1: Q4.1(B) R33.2
NetQ4_3: Q4.3(C) R26.2 ; port DIGITAL1
NetQ5_1: Q5.1(B) R41.1
NetQ6_1: Q6.1(B) R45.2
NetQ6_3: Q6.3(C) R42.2 ; port DIGITAL2
NetQ7_1: Q7.1(B) R51.1
NetQ8_1: Q8.1(B) R53.2
NetQ8_3: Q8.3(C) R48.2 U4.3(DE)
NetQ9_1: Q9.1(B) R58.2
NetQ9_3: Q9.3(C) R52.2 ; port DIGITAL3
NetQ10_1: Q10.1(B) R63.1
NetQ11_1: Q11.1(B) R67.2
NetQ11_3: Q11.3(C) R61.2 U5.3(DE)
NetQ12_1: Q12.1(B) R70.2
NetQ12_3: Q12.3(C) R64.2 ; port DIGITAL4
NetR20_2: R20.2 R21.1
NetR23_2: R23.2 ; port BATTERY_VOLTAGE
NetR28_2: R28.2 R29.1
NetR31_2: R31.2 ; port ANALOGUE_1
NetR32_2: R32.2 R33.1 R35.1
NetR36_2: R36.2 R37.1
NetR39_2: R39.2 ; port ANALOGUE_2
NetR44_2: R44.2 R45.1 R46.1
NetR47_2: R47.2 U4.4(D) ; port TX3_RS485_1
NetR53_1: R53.1 R56.1 ; port TX3ENABLE_RS485_1
NetR57_2: R57.2 R58.1 R59.1
NetR60_2: R60.2 U5.4(D) ; port TX4_RS485_2
NetR67_1: R67.1 R71.1 ; port TX4ENABLE_RS485_2
NetR69_2: R69.2 R70.1 R72.1
NetU3_57: U4.1(R) ; port RX3_RS485_1
NetU3_128: U5.1(R) ; port RX4_RS485_2

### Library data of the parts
C35 C36 C38-C41 C44 C46 = 100nF_0603N_50V_5%_X7R_V: as C13 on sheet Main-1
C37 C42 = 150pF_0603N_50V_5%_NP0_V: Cap Ceramic NP0; Manufacturer: Various; Part Number: 150pF 0603 50V 5% NP0; Board Tech: SMD; Tol: 5%
C43 C45 = DNF_0603N_50V_10%_X7R_V: as C33 on sheet Main-2
D11 D12 = SM4007_V: Diode Rectifier 1Amp 1000V; Manufacturer: Diotec; Board Tech: SMD; EDM-PN: DIO19
D13 D14 = SM4007_V-DNF: Diode Rectifier 1Amp 1000V - Do not Fit; Manufacturer: Diotec; Part Number: DNF-SM4007; Board Tech: SMD; EDM-PN: DIO19
J5 J7 = 8191-4-5.0: Screw Terminal 5.0mm Pitch; Manufacturer: Wieland; Board Tech: THP; EDM-PN: CON433; Value: 25.161.0453.0
P5 = DIL20P-2.54-DNF: Header Male Straight, 2.54mm Pitch - Do not Fit; Manufacturer: Various; Part Number: DNF - DIL20-P-2.54; Board Tech: THP
Q3 Q5 Q8 Q9 Q11 Q12 = BC817_SOT23: as Q1 on sheet Main-1
Q4 Q6 Q7 Q10 = BC817_SOT23-DNF: Transistor NPN General Purpose - Do not Fit; Manufacturer: Various; Part Number: DNF - BC817; Board Tech: SMD; EDM-PN: TRN12
R20 R21 R28 R29 R36 R37 = 1K8_0603_H: Resistor Chip SMD; Manufacturer: Various; Part Number: 1K8 0603 1%; Watt: 100mW
R22 R23 R30 R31 R38 R39 = 1K_0603_H: Resistor Chip SMD; Manufacturer: Various; Part Number: 1K 0603 1%; Watt: 100mW
R24 R34 R40 = 1K_0603_V: Resistor Chip SMD; Manufacturer: Various; Part Number: 1K 0603 1%; Watt: 100mW
R25 R41 R53 R67 = 2K2_0603_H: as R6 on sheet Main-1
R26 R42 = 390R_0603_H: Resistor Chip SMD; Manufacturer: Various; Part Number: 390R 0603 1%; Watt: 100mW
R27 R43 R56 R59 R71 R72 = 10K_0603_V: as R1 on sheet Main-1
R32 R33 R44 R45 R51 R52 R63 R64 = DNP_0603_H: Resistor Chip SMD; Manufacturer: Various; Watt: 100mW
R35 R46 R55 R66 = DNP_0603_V: Resistor Chip SMD; Manufacturer: Various; Watt: 100mW
R47 R48 R60 R61 = 3K3_0603_V: as R5 on sheet Main-1
R49 R54 R62 R68 = 560R_0603_V: Resistor Chip SMD; Manufacturer: Various; Part Number: 560R 0603 1%; Watt: 100mW
R50 R65 = 120R_1206_V-DNF: Resistor Chip SMD - Do not Fit; Manufacturer: Various; Part Number: DNF - 120R 1206 1%; Watt: 250mW
R57 R69 = 0R_0603_H: Resistor Chip SMD; Manufacturer: Various; Part Number: 0R 0603 1%; Watt: 100mW; EDM-PN: RES117
R58 R70 = 4K7_0603_H: Resistor Chip SMD; Manufacturer: Various; Part Number: 4K7 0603 1%; Watt: 100mW
U4 U5 = DS75176BM_SO8: IC 3.3V RS-485 Drivers and Receivers; Manufacturer: National; Board Tech: SMD

## Sheet Main-4.SchDoc: #
size A3; ApprovedBy: #; DrawnBy: #; DocumentNumber: 4; Revision: #; SheetNumber: 4; DocumentRevision: #; Reviewed: #; QA: #; CM: #; ECR: #; PageSetup: Record=PageOptions¦CenterHorizontal=True¦CenterVertical=True¦PrintScale=1.01¦XCorrection=1.00¦YCorrection=1.00¦PrintKind=1¦BorderSize=5000000¦LeftOffset=0¦BottomOffset=0¦Orientation=2¦PaperLength=1000¦PaperWidth=1000¦Scale=100¦PaperSource=7¦PrintQuality=-4¦MediaType=1¦DitherType=10¦PaperKind=A3¦PrintScaleMode=1
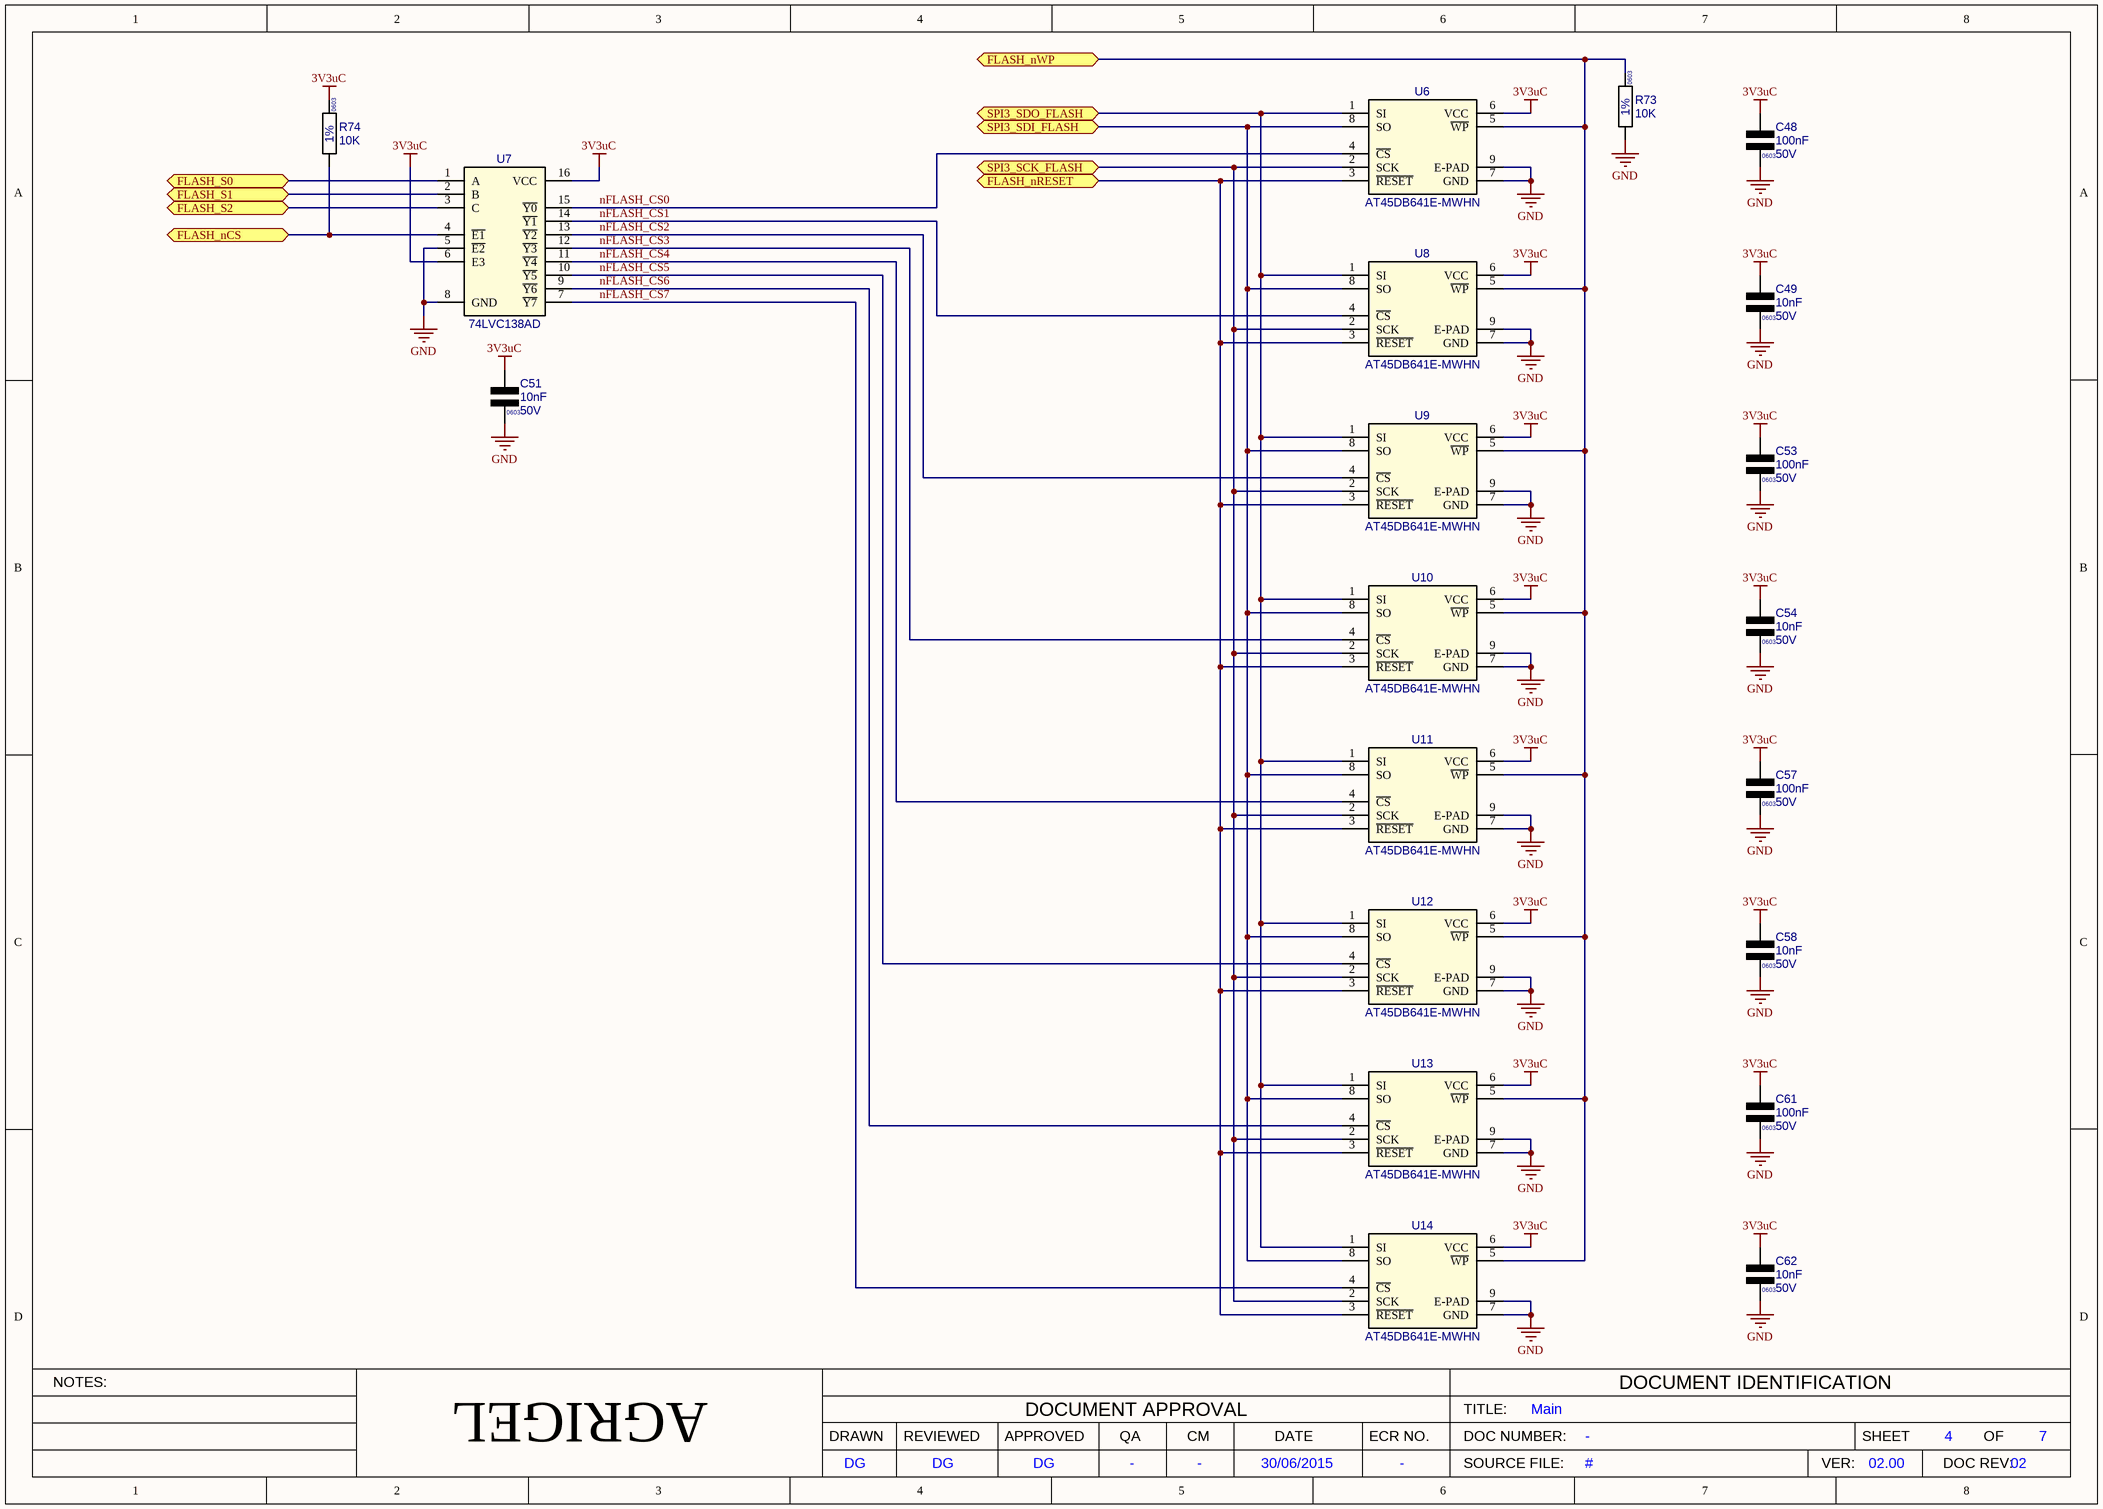
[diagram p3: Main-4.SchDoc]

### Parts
C48  value 100nF  Voltage: 50V  Text1: 0603  [CAPC0603X85N]  (hidden comment: 100nF_C0603_50V_5%_X7R)
C49  value 10nF  Voltage: 50V  Text1: 0603  [CAPC0603X85N]  (hidden comment: 10nF_C0603_50V_10%_X7R)
C51  value 10nF  Voltage: 50V  Text1: 0603  [CAPC0603X85N]  (hidden comment: 10nF_C0603_50V_10%_X7R)
C53  value 100nF  Voltage: 50V  Text1: 0603  [CAPC0603X85N]  (hidden comment: 100nF_C0603_50V_5%_X7R)
C54  value 10nF  Voltage: 50V  Text1: 0603  [CAPC0603X85N]  (hidden comment: 10nF_C0603_50V_10%_X7R)
C57  value 100nF  Voltage: 50V  Text1: 0603  [CAPC0603X85N]  (hidden comment: 100nF_C0603_50V_5%_X7R)
C58  value 10nF  Voltage: 50V  Text1: 0603  [CAPC0603X85N]  (hidden comment: 10nF_C0603_50V_10%_X7R)
C61  value 100nF  Voltage: 50V  Text1: 0603  [CAPC0603X85N]  (hidden comment: 100nF_C0603_50V_5%_X7R)
C62  value 10nF  Voltage: 50V  Text1: 0603  [CAPC0603X85N]  (hidden comment: 10nF_C0603_50V_10%_X7R)
R73  value 10K  Tol: 1%  Text1: 0603  [RESC0603X60N]  (hidden comment: 10K_R0603_1%)
R74  value 10K  Tol: 1%  Text1: 0603  [RESC0603X60N]  (hidden comment: 10K_R0603_1%)
U6  AT45DB641E-MWHN  [UDFN8-6x5-EP]
U7  74LVC138AD  [SO16]
U8  AT45DB641E-MWHN  [UDFN8-6x5-EP]
U9  AT45DB641E-MWHN  [UDFN8-6x5-EP]
U10  AT45DB641E-MWHN  [UDFN8-6x5-EP]
U11  AT45DB641E-MWHN  [UDFN8-6x5-EP]
U12  AT45DB641E-MWHN  [UDFN8-6x5-EP]
U13  AT45DB641E-MWHN  [UDFN8-6x5-EP]
U14  AT45DB641E-MWHN  [UDFN8-6x5-EP]

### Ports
FLASH_nCS, FLASH_nRESET, FLASH_nWP, FLASH_S0, FLASH_S1, FLASH_S2, SPI3_SCK_FLASH, SPI3_SDI_FLASH, SPI3_SDO_FLASH

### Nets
3V3uC: C48.1 C49.1 C51.1 C53.1 C54.1 C57.1 C58.1 C61.1 C62.1 R74.1 U6.6(VCC) U7.6(E3) U7.16(VCC) U8.6(VCC) U9.6(VCC) U10.6(VCC) U11.6(VCC) U12.6(VCC) U13.6(VCC) U14.6(VCC)
GND: C48.2 C49.2 C51.2 C53.2 C54.2 C57.2 C58.2 C61.2 C62.2 R73.2 U6.7(GND) U6.9(E-PAD) U7.5(~{E2}) U7.8(GND) U8.7(GND) U8.9(E-PAD) U9.7(GND) U9.9(E-PAD) U10.7(GND) U10.9(E-PAD) U11.7(GND) U11.9(E-PAD) U12.7(GND) U12.9(E-PAD) U13.7(GND) U13.9(E-PAD) U14.7(GND) U14.9(E-PAD)
nFLASH_CS0: U6.4(~{CS}) U7.15(~{Y0})
nFLASH_CS1: U7.14(~{Y1}) U8.4(~{CS})
nFLASH_CS2: U7.13(~{Y2}) U9.4(~{CS})
nFLASH_CS3: U7.12(~{Y3}) U10.4(~{CS})
nFLASH_CS4: U7.11(~{Y4}) U11.4(~{CS})
nFLASH_CS5: U7.10(~{Y5}) U12.4(~{CS})
nFLASH_CS6: U7.9(~{Y6}) U13.4(~{CS})
nFLASH_CS7: U7.7(~{Y7}) U14.4(~{CS})
NetR73_1: R73.1 U6.5(~{WP}) U8.5(~{WP}) U9.5(~{WP}) U10.5(~{WP}) U11.5(~{WP}) U12.5(~{WP}) U13.5(~{WP}) U14.5(~{WP}) ; port FLASH_nWP
NetR74_2: R74.2 U7.4(~{E1}) ; port FLASH_nCS
NetU3_49: U6.3(~{RESET}) U8.3(~{RESET}) U9.3(~{RESET}) U10.3(~{RESET}) U11.3(~{RESET}) U12.3(~{RESET}) U13.3(~{RESET}) U14.3(~{RESET}) ; port FLASH_nRESET
NetU3_60: U7.1(A) ; port FLASH_S0
NetU3_61: U7.2(B) ; port FLASH_S1
NetU3_62: U7.3(C) ; port FLASH_S2
NetU3_69: U6.8(SO) U8.8(SO) U9.8(SO) U10.8(SO) U11.8(SO) U12.8(SO) U13.8(SO) U14.8(SO) ; port SPI3_SDI_FLASH
NetU3_70: U6.1(SI) U8.1(SI) U9.1(SI) U10.1(SI) U11.1(SI) U12.1(SI) U13.1(SI) U14.1(SI) ; port SPI3_SDO_FLASH
NetU3_71: U6.2(SCK) U8.2(SCK) U9.2(SCK) U10.2(SCK) U11.2(SCK) U12.2(SCK) U13.2(SCK) U14.2(SCK) ; port SPI3_SCK_FLASH

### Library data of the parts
C48 C53 C57 C61 = 100nF_0603N_50V_5%_X7R_V: as C13 on sheet Main-1
C49 C51 C54 C58 C62 = 10nF_0603N_50V_10%_X7R_V: as C12 on sheet Main-1
R73 R74 = 10K_0603_V: as R1 on sheet Main-1
U6 U8-U14 = AT45DB641E-MWHN_UDFN: IC 64Mbit Dual-IF Dataflash; Manufacturer: Adesto; Board Tech: SMD
U7 = 74LVC138AD_SO16: IC 3-Line to 8-Line Decoder / Demultplexer; Manufacturer: NXP; Board Tech: SMD

## Sheet Main-5.SchDoc: #
size A3; ApprovedBy: #; DrawnBy: #; DocumentNumber: 5; Revision: #; SheetNumber: 5; DocumentRevision: #; Reviewed: #; QA: #; CM: #; ECR: #; PageSetup: Record=PageOptions¦CenterHorizontal=True¦CenterVertical=True¦PrintScale=0.97¦XCorrection=1.00¦YCorrection=1.00¦PrintKind=1¦BorderSize=5000000¦LeftOffset=0¦BottomOffset=0¦Orientation=2¦PaperLength=1000¦PaperWidth=1000¦Scale=100¦PaperSource=7¦PrintQuality=-4¦MediaType=1¦DitherType=10¦PaperKind=A3¦PrintScaleMode=1
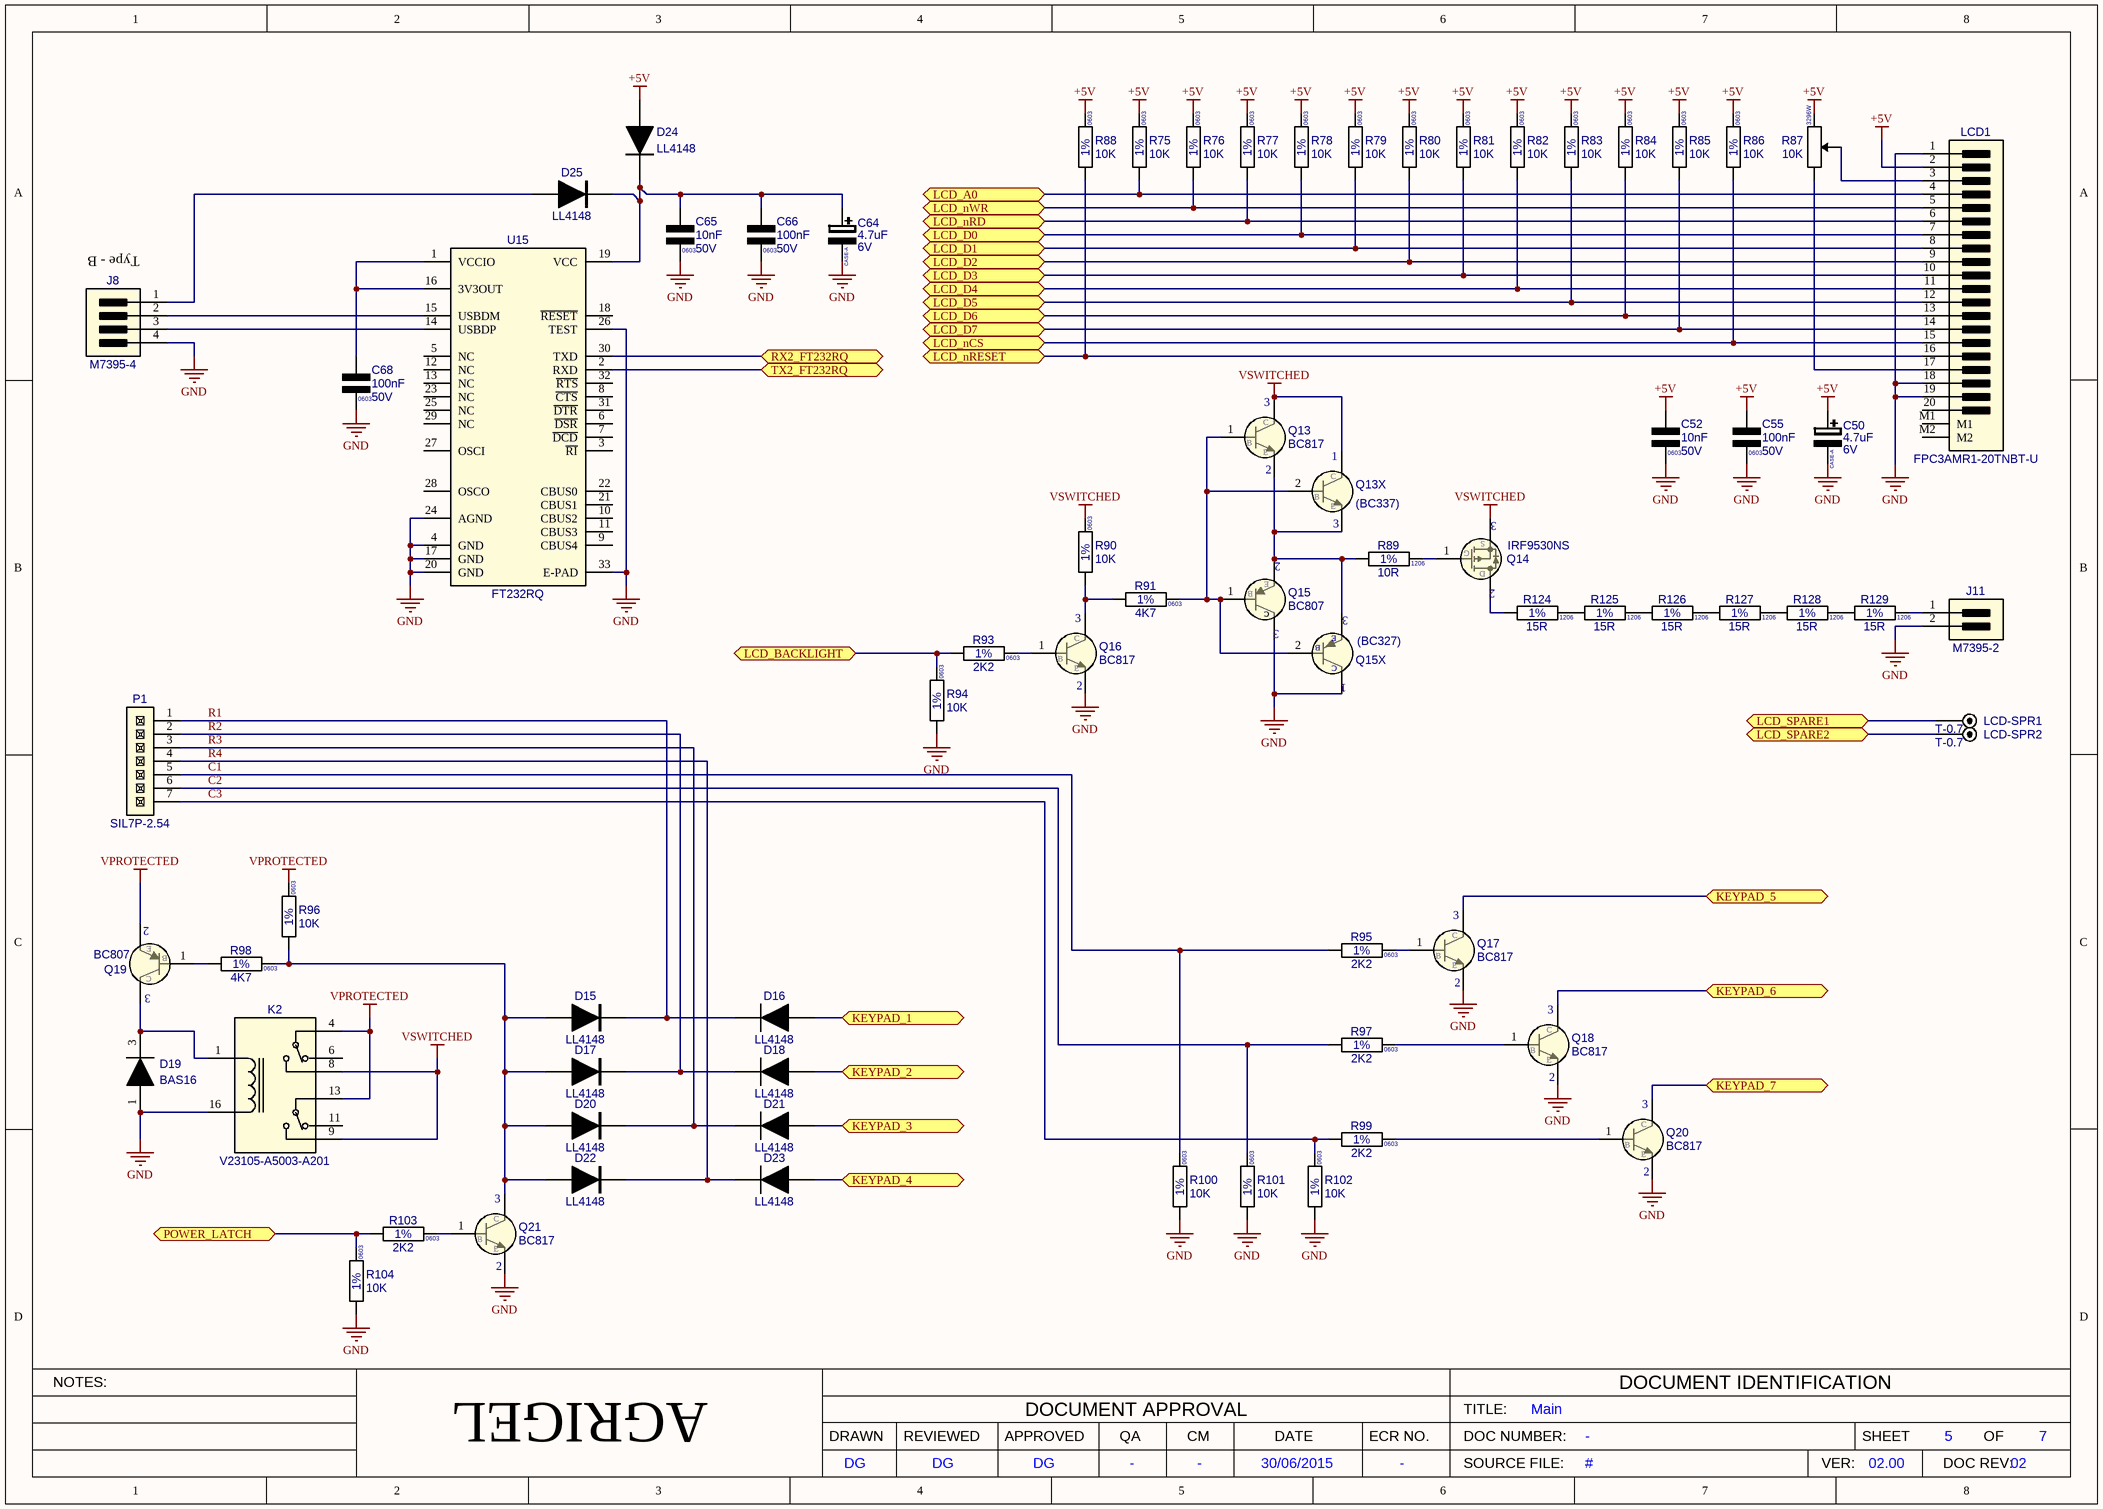
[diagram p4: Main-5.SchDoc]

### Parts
C50  value 4.7uF  Voltage: 6V  Text1: CASE-A  [T491-A]  (hidden comment: 4.7uF_6V_T491A_20%)
C52  value 10nF  Voltage: 50V  Text1: 0603  [CAPC0603X85N]  (hidden comment: 10nF_C0603_50V_10%_X7R)
C55  value 100nF  Voltage: 50V  Text1: 0603  [CAPC0603X85N]  (hidden comment: 100nF_C0603_50V_5%_X7R)
C64  value 4.7uF  Voltage: 6V  Text1: CASE-A  [T491-A]  (hidden comment: 4.7uF_6V_T491A_20%)
C65  value 10nF  Voltage: 50V  Text1: 0603  [CAPC0603X85N]  (hidden comment: 10nF_C0603_50V_10%_X7R)
C66  value 100nF  Voltage: 50V  Text1: 0603  [CAPC0603X85N]  (hidden comment: 100nF_C0603_50V_5%_X7R)
C68  value 100nF  Voltage: 50V  Text1: 0603  [CAPC0603X85N]  (hidden comment: 100nF_C0603_50V_5%_X7R)
D15  LL4148  [SOD80]
D16  LL4148  [SOD80]
D17  LL4148  [SOD80]
D18  LL4148  [SOD80]
D19  BAS16  [SOT23]
D20  LL4148  [SOD80]
D21  LL4148  [SOD80]
D22  LL4148  [SOD80]
D23  LL4148  [SOD80]
D24  LL4148  [SOD80]
D25  LL4148  [SOD80]
J8  M7395-4  [M7395-4]
J11  M7395-2  [M7395-2]
K2  Part Number: V23105-A5003-A201  [REL-D2n]  (hidden comment: V23105-A5003-A201-12V)
LCD1  Part Number: FPC3AMR1-20TNBT-U  [FPC3AMR1-20-B-U]  (hidden comment: FPC3AMR1-20TNBT-U-Bottom)
LCD-SPR1  Part Number: T-0.7  [TP-THP-0.7mm]  (hidden comment: TP-THP-0.7MM)
LCD-SPR2  Part Number: T-0.7  [TP-THP-0.7mm]  (hidden comment: TP-THP-0.7MM)
P1  SIL7P-2.54  [SIL7P-2.54]
Q13  BC817  [SOT23]
Q13X  value (BC337)  [TO-92]  (hidden comment: BC337-DNF)
Q14  IRF9530NS  [D2PAK]
Q15  BC807  [SOT23]
Q15X  value (BC327)  [TO-92]  (hidden comment: BC327-DNF)
Q16  BC817  [SOT23]
Q17  BC817  [SOT23]
Q18  BC817  [SOT23]
Q19  BC807  [SOT23]
Q20  BC817  [SOT23]
Q21  BC817  [SOT23]
R75  value 10K  Tol: 1%  Text1: 0603  [RESC0603X60N]  (hidden comment: 10K_R0603_1%)
R76  value 10K  Tol: 1%  Text1: 0603  [RESC0603X60N]  (hidden comment: 10K_R0603_1%)
R77  value 10K  Tol: 1%  Text1: 0603  [RESC0603X60N]  (hidden comment: 10K_R0603_1%)
R78  value 10K  Tol: 1%  Text1: 0603  [RESC0603X60N]  (hidden comment: 10K_R0603_1%)
R79  value 10K  Tol: 1%  Text1: 0603  [RESC0603X60N]  (hidden comment: 10K_R0603_1%)
R80  value 10K  Tol: 1%  Text1: 0603  [RESC0603X60N]  (hidden comment: 10K_R0603_1%)
R81  value 10K  Tol: 1%  Text1: 0603  [RESC0603X60N]  (hidden comment: 10K_R0603_1%)
R82  value 10K  Tol: 1%  Text1: 0603  [RESC0603X60N]  (hidden comment: 10K_R0603_1%)
R83  value 10K  Tol: 1%  Text1: 0603  [RESC0603X60N]  (hidden comment: 10K_R0603_1%)
R84  value 10K  Tol: 1%  Text1: 0603  [RESC0603X60N]  (hidden comment: 10K_R0603_1%)
R85  value 10K  Tol: 1%  Text1: 0603  [RESC0603X60N]  (hidden comment: 10K_R0603_1%)
R86  value 10K  Tol: 1%  Text1: 0603  [RESC0603X60N]  (hidden comment: 10K_R0603_1%)
R87  value 10K  Text1: 3296W  [3296W-THP]  (hidden comment: 3296W-1-103)
R88  value 10K  Tol: 1%  Text1: 0603  [RESC0603X60N]  (hidden comment: 10K_R0603_1%)
R89  value 10R  Tol: 1%  Text1: 1206  [RESC1206X71N]  (hidden comment: 10R_R1206_1%)
R90  value 10K  Tol: 1%  Text1: 0603  [RESC0603X60N]  (hidden comment: 10K_R0603_1%)
R91  value 4K7  Tol: 1%  Text1: 0603  [RESC0603X60N]  (hidden comment: 4K7_R0603_1%)
R93  value 2K2  Tol: 1%  Text1: 0603  [RESC0603X60N]  (hidden comment: 2K2_R0603_1%)
R94  value 10K  Tol: 1%  Text1: 0603  [RESC0603X60N]  (hidden comment: 10K_R0603_1%)
R95  value 2K2  Tol: 1%  Text1: 0603  [RESC0603X60N]  (hidden comment: 2K2_R0603_1%)
R96  value 10K  Tol: 1%  Text1: 0603  [RESC0603X60N]  (hidden comment: 10K_R0603_1%)
R97  value 2K2  Tol: 1%  Text1: 0603  [RESC0603X60N]  (hidden comment: 2K2_R0603_1%)
R98  value 4K7  Tol: 1%  Text1: 0603  [RESC0603X60N]  (hidden comment: 4K7_R0603_1%)
R99  value 2K2  Tol: 1%  Text1: 0603  [RESC0603X60N]  (hidden comment: 2K2_R0603_1%)
R100  value 10K  Tol: 1%  Text1: 0603  [RESC0603X60N]  (hidden comment: 10K_R0603_1%)
R101  value 10K  Tol: 1%  Text1: 0603  [RESC0603X60N]  (hidden comment: 10K_R0603_1%)
R102  value 10K  Tol: 1%  Text1: 0603  [RESC0603X60N]  (hidden comment: 10K_R0603_1%)
R103  value 2K2  Tol: 1%  Text1: 0603  [RESC0603X60N]  (hidden comment: 2K2_R0603_1%)
R104  value 10K  Tol: 1%  Text1: 0603  [RESC0603X60N]  (hidden comment: 10K_R0603_1%)
R124  value 15R  Tol: 1%  Text1: 1206  [RESC1206X71N]  (hidden comment: 15R_R1206_1%)
R125  value 15R  Tol: 1%  Text1: 1206  [RESC1206X71N]  (hidden comment: 15R_R1206_1%)
R126  value 15R  Tol: 1%  Text1: 1206  [RESC1206X71N]  (hidden comment: 15R_R1206_1%)
R127  value 15R  Tol: 1%  Text1: 1206  [RESC1206X71N]  (hidden comment: 15R_R1206_1%)
R128  value 15R  Tol: 1%  Text1: 1206  [RESC1206X71N]  (hidden comment: 15R_R1206_1%)
R129  value 15R  Tol: 1%  Text1: 1206  [RESC1206X71N]  (hidden comment: 15R_R1206_1%)
U15  FT232RQ  [QFN32-5x5-FT232]

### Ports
KEYPAD_1, KEYPAD_2, KEYPAD_3, KEYPAD_4, KEYPAD_5, KEYPAD_6, KEYPAD_7, LCD_A0, LCD_BACKLIGHT, LCD_D0, LCD_D1, LCD_D2, LCD_D3, LCD_D4, LCD_D5, LCD_D6, LCD_D7, LCD_nCS, LCD_nRD, LCD_nRESET, LCD_nWR, LCD_SPARE1, LCD_SPARE2, POWER_LATCH, RX2_FT232RQ, TX2_FT232RQ

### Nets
+5V: C50.1 C52.1 C55.1 D24.2(A) LCD1.2 R75.1 R76.1 R77.1 R78.1 R79.1 R80.1 R81.1 R82.1 R83.1 R84.1 R85.1 R86.1 R87.1 R88.1
GND: C50.2 C52.2 C55.2 C64.2 C65.2 C66.2 C68.2 D19.1(A) J8.4 J11.2 K2.16 LCD1.1 LCD1.18 LCD1.19 Q15.3(C) Q15X.1(C) Q16.2(E) Q17.2(E) Q18.2(E) Q20.2(E) Q21.2(E) R94.2 R100.2 R101.2 R102.2 R104.2 U15.4(GND) U15.17(GND) U15.20(GND) U15.24(AGND) U15.26(TEST) U15.33(E-PAD)
VPROTECTED: K2.4 K2.13 Q19.2(E) R96.1
VSWITCHED: K2.8 K2.9 Q13.3(C) Q13X.1(C) Q14.3(S) R90.1
C1: P1.5 R95.1 R100.1
C2: P1.6 R97.1 R101.1
C3: P1.7 R99.1 R102.1
R1: D15.1(C) D16.1(C) P1.1
R2: D17.1(C) D18.1(C) P1.2
R3: D20.1(C) D21.1(C) P1.3
R4: D22.1(C) D23.1(C) P1.4
NetC64_1: C64.1 C65.1 C66.1 D24.1(C) D25.1(C) U15.19(VCC)
NetC68_1: C68.1 U15.1(VCCIO) U15.16(3V3OUT)
NetD15_2: D15.2(A) D17.2(A) D20.2(A) D22.2(A) Q21.3(C) R96.2 R98.2
NetD16_2: D16.2(A) ; port KEYPAD_1
NetD18_2: D18.2(A) ; port KEYPAD_2
NetD19_3: D19.3(C) K2.1 Q19.3(C)
NetD21_2: D21.2(A) ; port KEYPAD_3
NetD23_2: D23.2(A) ; port KEYPAD_4
NetD25_2: D25.2(A) J8.1
NetJ8_2: J8.2 U15.15(USBDM)
NetJ8_3: J8.3 U15.14(USBDP)
NetJ11_1: J11.1 R129.2
NetLCD1_3: LCD1.3 R87.2
NetLCD1_4: LCD1.4 R75.2 ; port LCD_A0
NetLCD1_5: LCD1.5 R76.2 ; port LCD_nWR
NetLCD1_6: LCD1.6 R77.2 ; port LCD_nRD
NetLCD1_7: LCD1.7 R78.2 ; port LCD_D0
NetLCD1_8: LCD1.8 R79.2 ; port LCD_D1
NetLCD1_9: LCD1.9 R80.2 ; port LCD_D2
NetLCD1_10: LCD1.10 R81.2 ; port LCD_D3
NetLCD1_11: LCD1.11 R82.2 ; port LCD_D4
NetLCD1_12: LCD1.12 R83.2 ; port LCD_D5
NetLCD1_13: LCD1.13 R84.2 ; port LCD_D6
NetLCD1_14: LCD1.14 R85.2 ; port LCD_D7
NetLCD1_15: LCD1.15 R86.2 ; port LCD_nCS
NetLCD1_16: LCD1.16 R88.2 ; port LCD_nRESET
NetLCD1_17: LCD1.17 R87.3
NetLCD-SPR1_1: LCD-SPR1.1 ; port LCD_SPARE1
NetLCD-SPR2_1: LCD-SPR2.1 ; port LCD_SPARE2
NetQ13_1: Q13.1(B) Q13X.2(B) Q15.1(B) Q15X.2(B) R91.2
NetQ13_2: Q13.2(E) Q13X.3(E) Q15.2(E) Q15X.3(E) R89.1
NetQ14_1: Q14.1(G) R89.2
NetQ14_2: Q14.2(D) R124.1
NetQ16_1: Q16.1(B) R93.2
NetQ16_3: Q16.3(C) R90.2 R91.1
NetQ17_1: Q17.1(B) R95.2
NetQ17_3: Q17.3(C) ; port KEYPAD_5
NetQ18_1: Q18.1(B) R97.2
NetQ18_3: Q18.3(C) ; port KEYPAD_6
NetQ19_1: Q19.1(B) R98.1
NetQ20_1: Q20.1(B) R99.2
NetQ20_3: Q20.3(C) ; port KEYPAD_7
NetQ21_1: Q21.1(B) R103.2
NetR93_1: R93.1 R94.1 ; port LCD_BACKLIGHT
NetR103_1: R103.1 R104.1 ; port POWER_LATCH
NetR124_2: R124.2 R125.1
NetR125_2: R125.2 R126.1
NetR126_2: R126.2 R127.1
NetR127_2: R127.2 R128.1
NetR128_2: R128.2 R129.1
NetU3_136: U15.2(RXD) ; port TX2_FT232RQ
NetU3_137: U15.30(TXD) ; port RX2_FT232RQ

Not connected (* = marked no-connect by the designer): K2 6 11; LCD1 20 M1 M2; U15 3(~{RI}) 5(NC) 6(~{DSR}) 7(~{DCD}) 8(~{CTS}) 9(CBUS4) 10(CBUS2) 11(CBUS3) 12(NC) 13(NC) 18(~{RESET}) 21(CBUS1) 22(CBUS0) 23(NC) 25(NC) 27(OSCI) 28(OSCO) 29(NC) 31(~{DTR}) 32(~{RTS})

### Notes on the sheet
- (near J8) Type - B
- (near Q15) C

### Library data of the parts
C50 C64 = 4.7uF_6V_CASE-A_20%_V: Cap Tantalum Case-A; Manufacturer: Various; Board Tech: SMD; Tol: 20%
C52 C65 = 10nF_0603N_50V_10%_X7R_V: as C12 on sheet Main-1
C55 C66 C68 = 100nF_0603N_50V_5%_X7R_V: as C13 on sheet Main-1
D15-D18 D20-D23 D25 = LL4148_MELF_H: Diode Fast Switching Surface Mount; Manufacturer: DIODES INC; Board Tech: SMD
D19 = BAS16_SOT23-3N_V: as D2 on sheet Main-1
D24 = LL4148_MELF_X: Diode Fast Switching Surface Mount; Manufacturer: DIODES INC; Board Tech: SMD
J8 = M7395-4: Header Pluggable 2.54mm Rt Angle Friction Lock; Manufacturer: Molex; Board Tech: THP
J11 = M7395-2: Header Pluggable 2.54mm Rt Angle Friction Lock; Manufacturer: Molex; Board Tech: THP
K2 = V23105-A5003-A201-12V: as K1 on sheet Main-1
LCD1 = FPC3AMR1-20TNBT-U-Bottom: ZIF Connector, 1.0mm Contact Pitch Bottom; Manufacturer: Amtek; Board Tech: SMD
LCD-SPR1 LCD-SPR2 = TP-THP-0.7MM: Test Point Through Hole Plated 0.7mm Hole; Manufacturer: Generic; Board Tech: THP
P1 = SIL7P-2.54: Header SIL Male THP, 2.54mm Pitch; Manufacturer: Various
Q13 Q16-Q18 Q20 Q21 = BC817_SOT23: as Q1 on sheet Main-1
Q13X = BC337_TO-92-DNF: Transistor NPN Amplifier - Do not Fit; Manufacturer: On Semi; Part Number: DNF - BC337; Board Tech: THP
Q14 = IRF9530NS_D2PAK: FET P-Channel 14A 100V; Manufacturer: IRF; Board Tech: SMD
Q15 Q19 = BC807_SOT23-3N: Transistor PNP General Purpose; Manufacturer: NXP; Board Tech: SMD
Q15X = BC327_TO-92-DNF: Transistor PNP Amplifier - Do not Fit; Manufacturer: On Semi; Part Number: DNF - BC327; Board Tech: THP
R75-R86 R88 R90 R94 R96 R100-R102 R104 = 10K_0603_V: as R1 on sheet Main-1
R87 = 10K_3296W-1-103_THP_V: Variable Resistor THP; Manufacturer: BOURNS
R89 = 10R_1206_H: Resistor Chip SMD; Manufacturer: Various; Part Number: 10R 1206 1%; Watt: 250mW
R91 R98 = 4K7_0603_H: as R58 on sheet Main-3
R93 R95 R97 R99 R103 = 2K2_0603_H: as R6 on sheet Main-1
R124-R129 = 15R_1206_H: Resistor Chip SMD; Manufacturer: Various; Part Number: 15R 1206 1%; Watt: 250mW
U15 = FT232RQ_QFN32: IC USB UART; Manufacturer: FTDI; Board Tech: SMD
